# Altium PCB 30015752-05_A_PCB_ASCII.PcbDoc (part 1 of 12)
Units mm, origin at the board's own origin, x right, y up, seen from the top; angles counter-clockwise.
Board outline 100.05 x 72 mm, 10 copper layers (Top, GND_2, Signal_3, Signal_4, PWR_5, GND_6, Signal_7, Signal_8, GND_9, Bottom), stack 1.493 mm thick; 577 components, 546 nets, 2389 pads, 1412 vias.
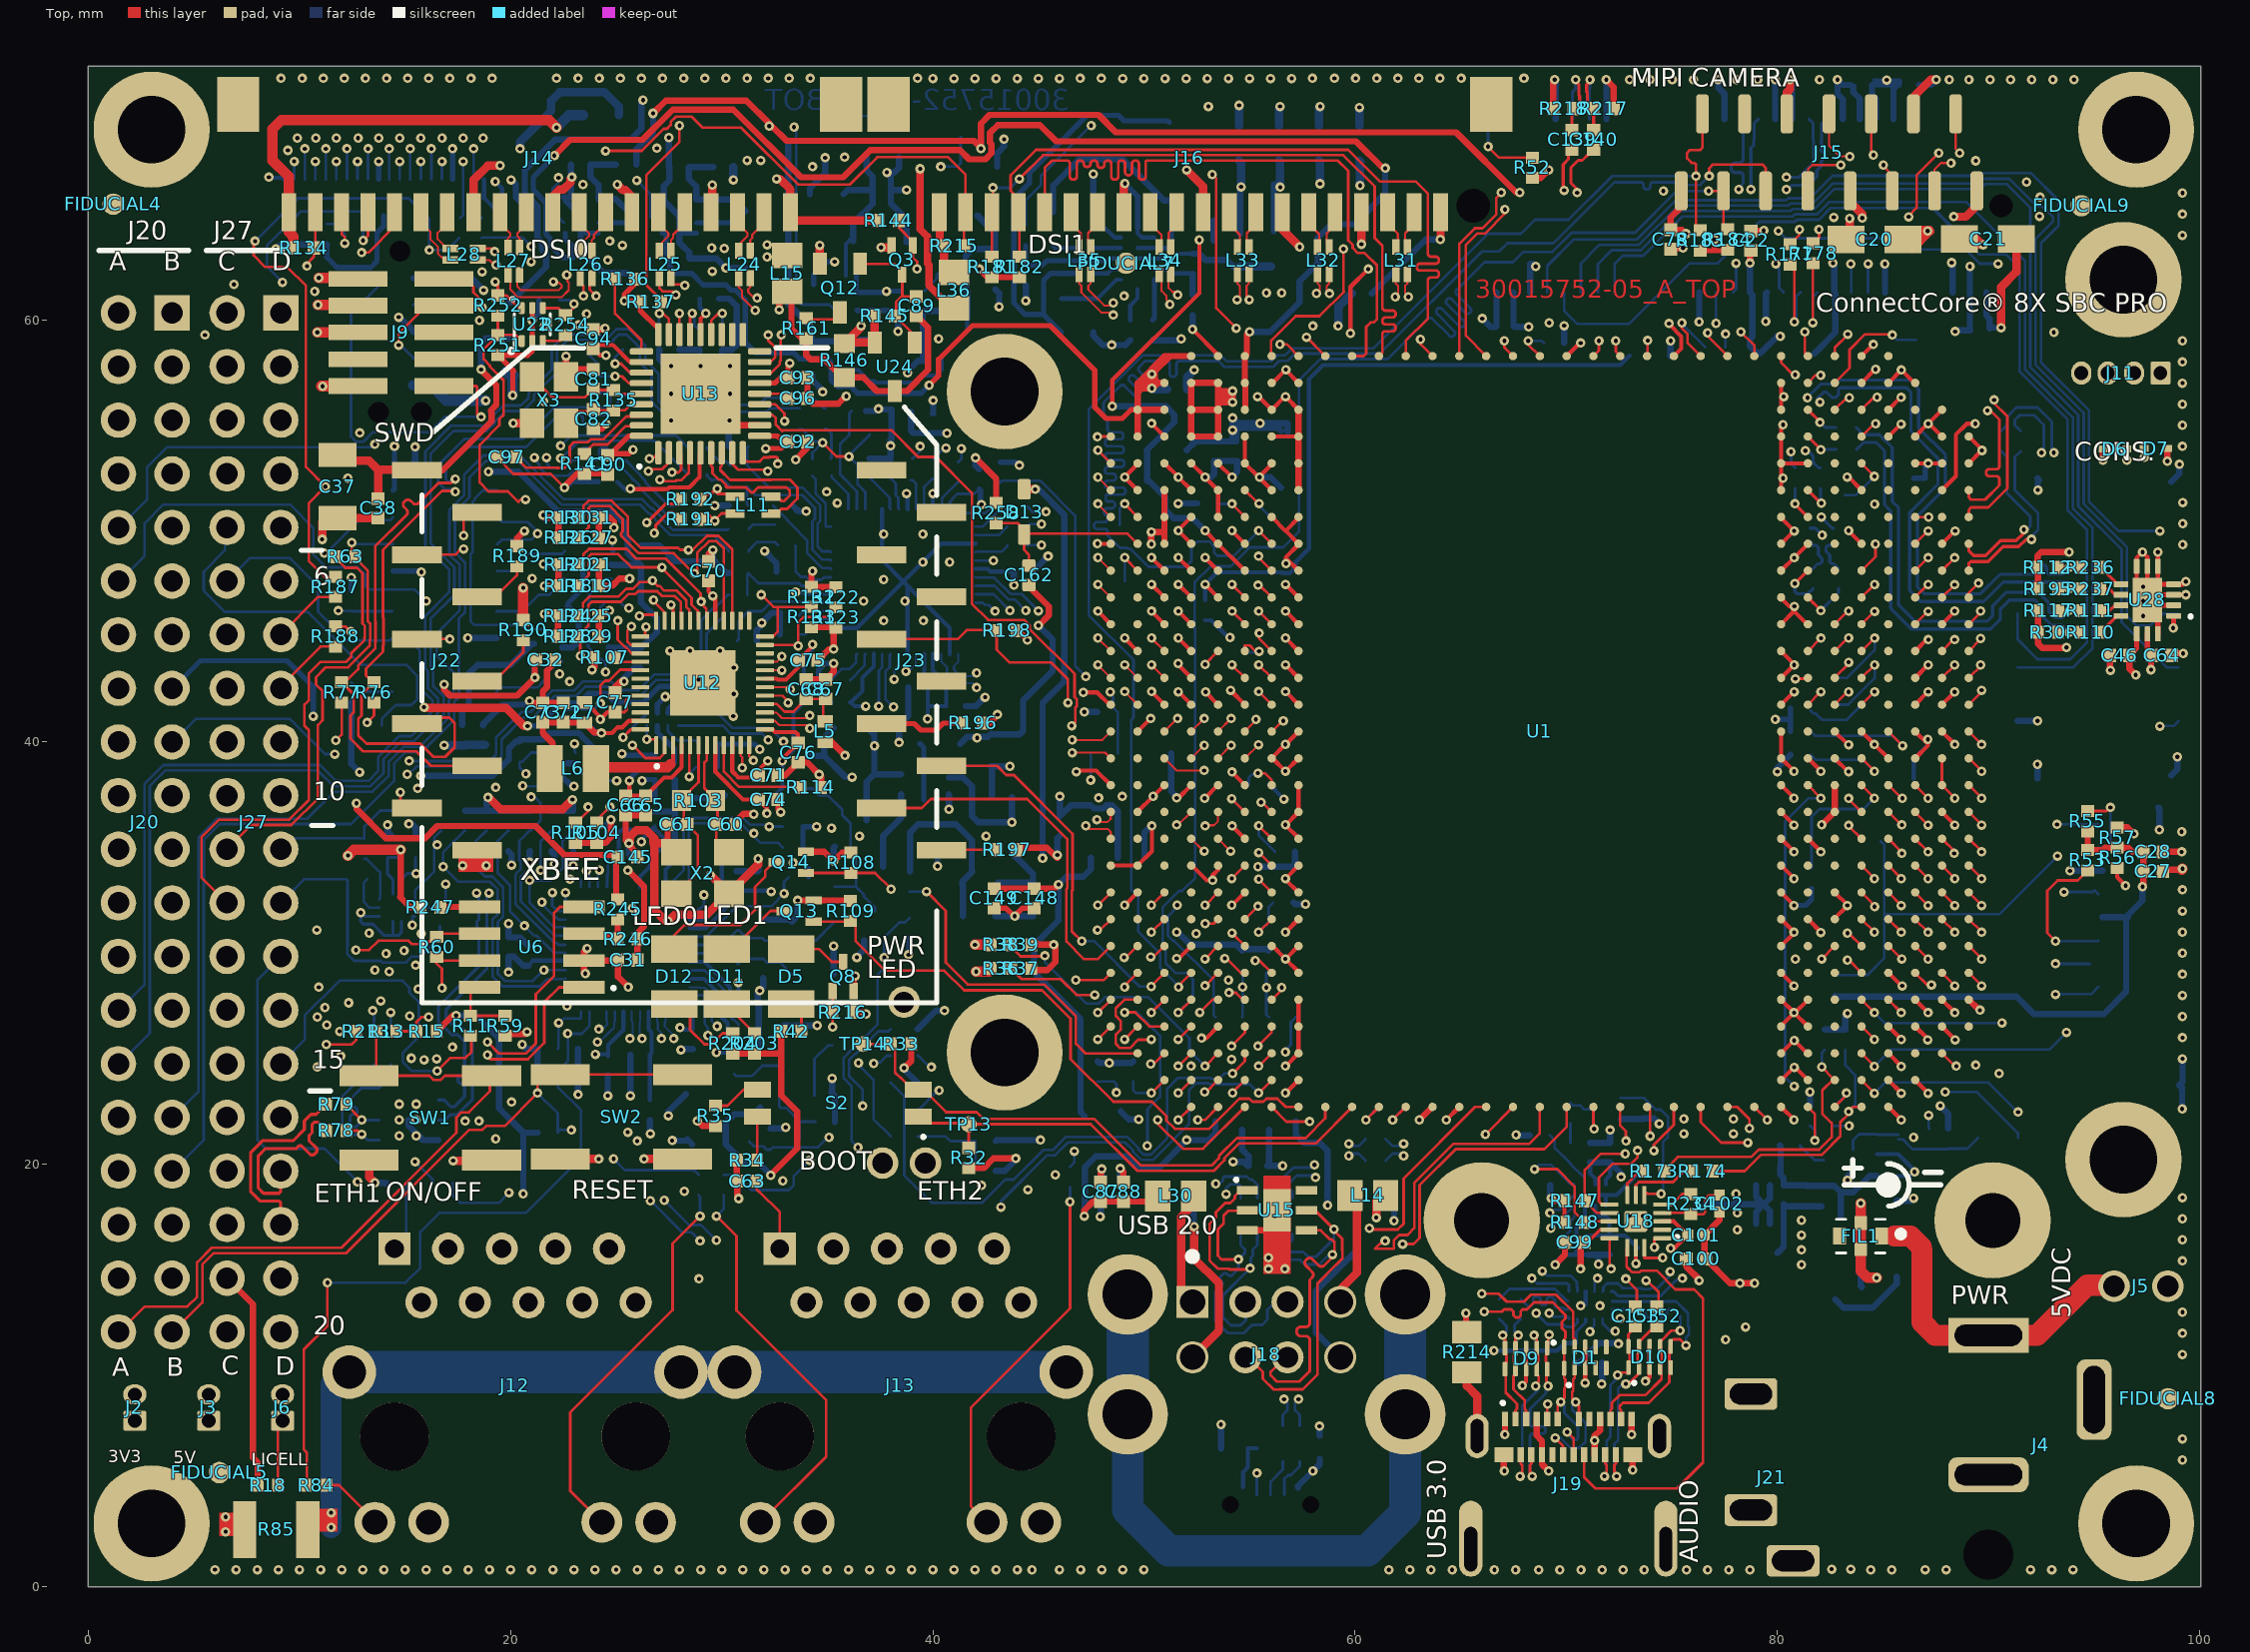
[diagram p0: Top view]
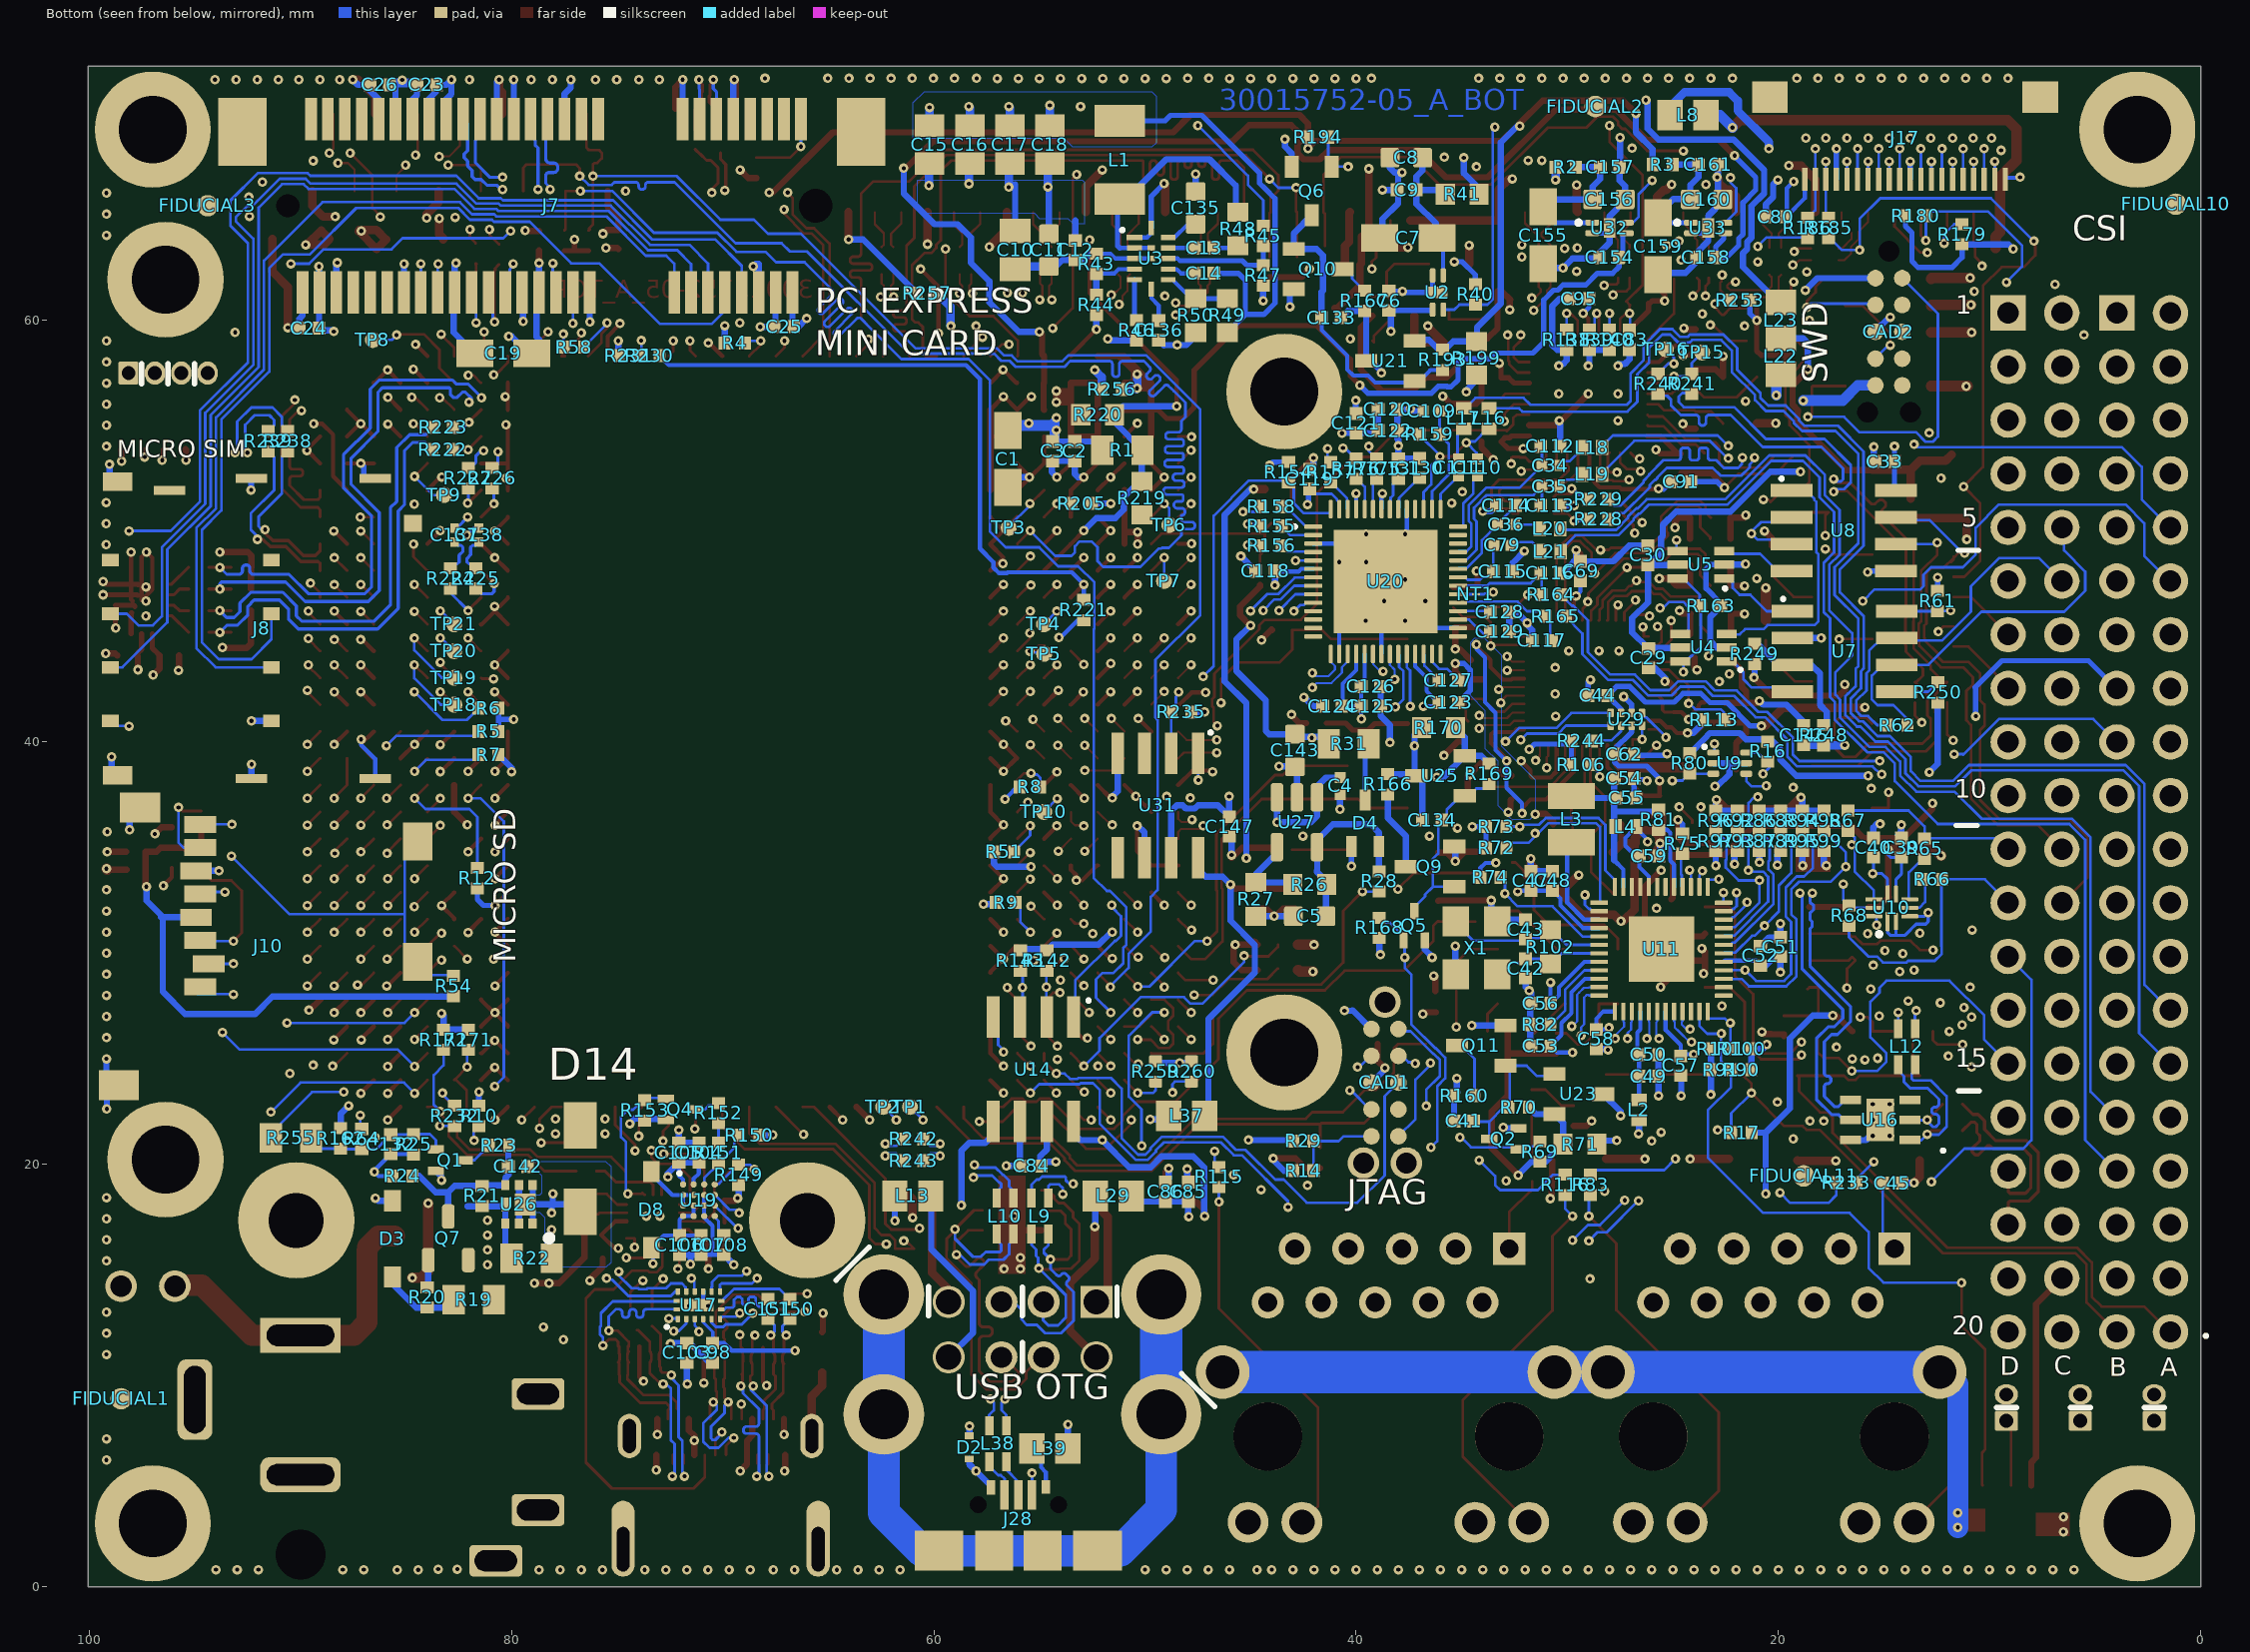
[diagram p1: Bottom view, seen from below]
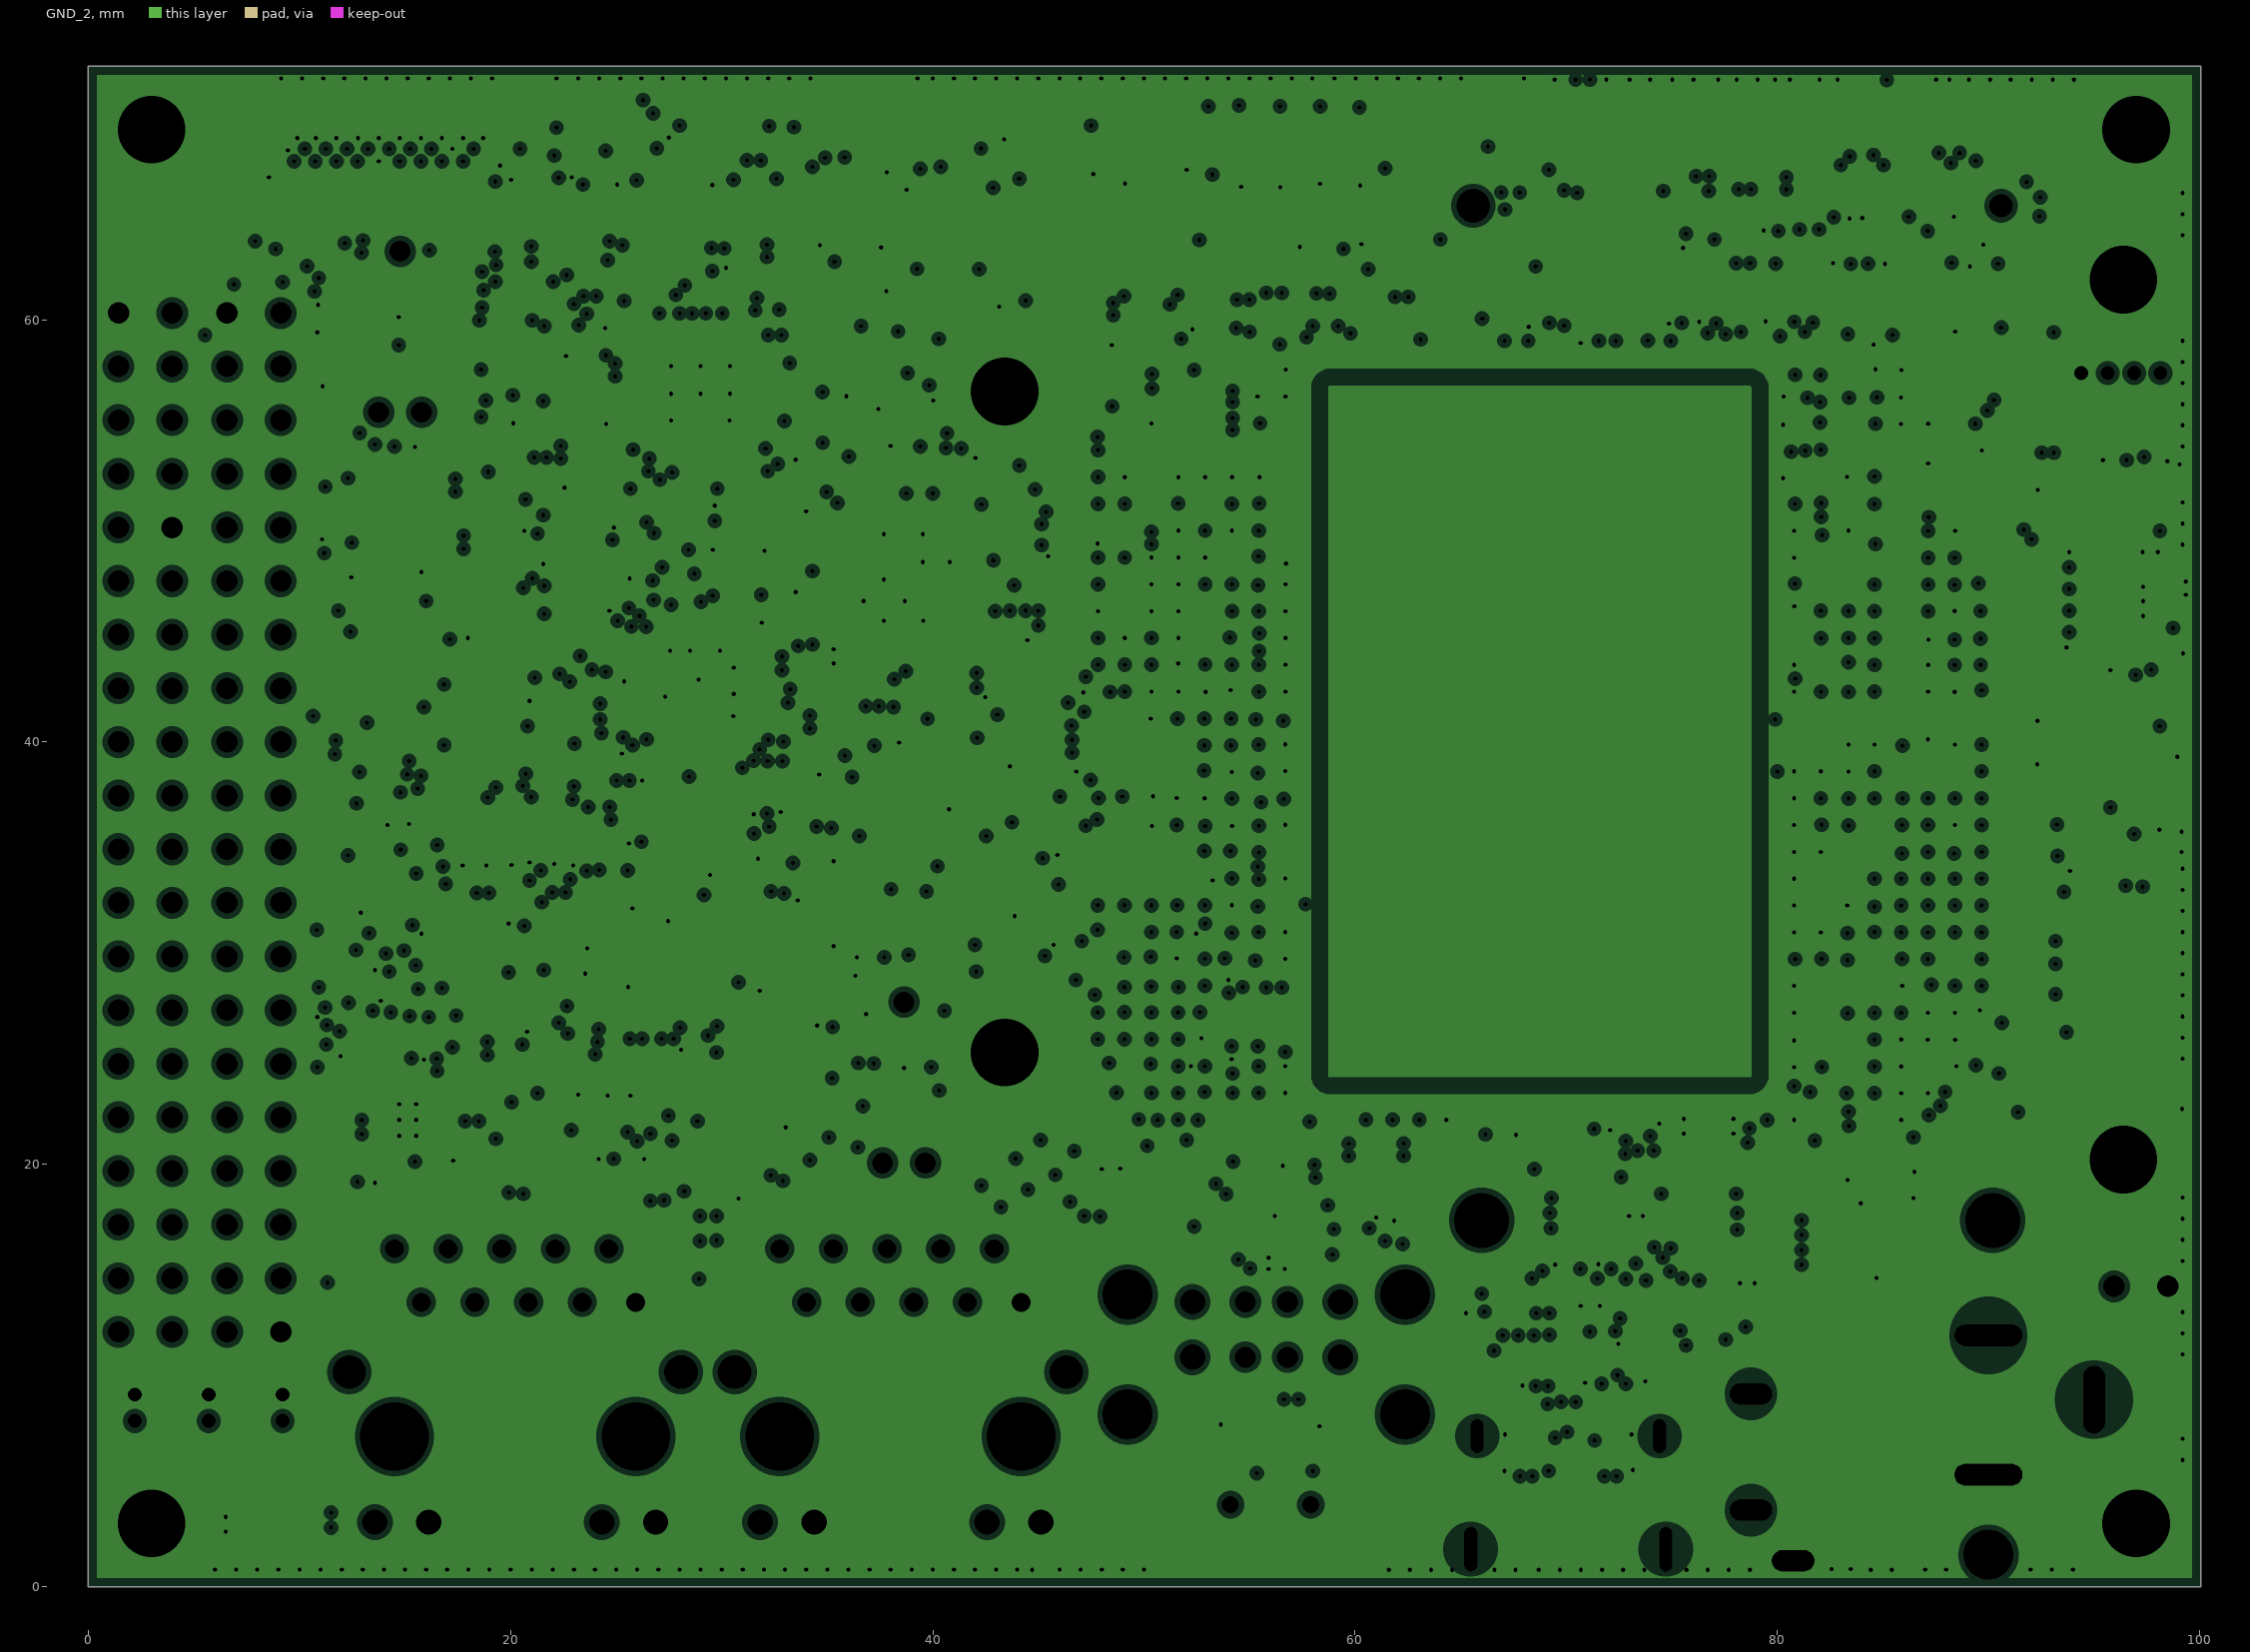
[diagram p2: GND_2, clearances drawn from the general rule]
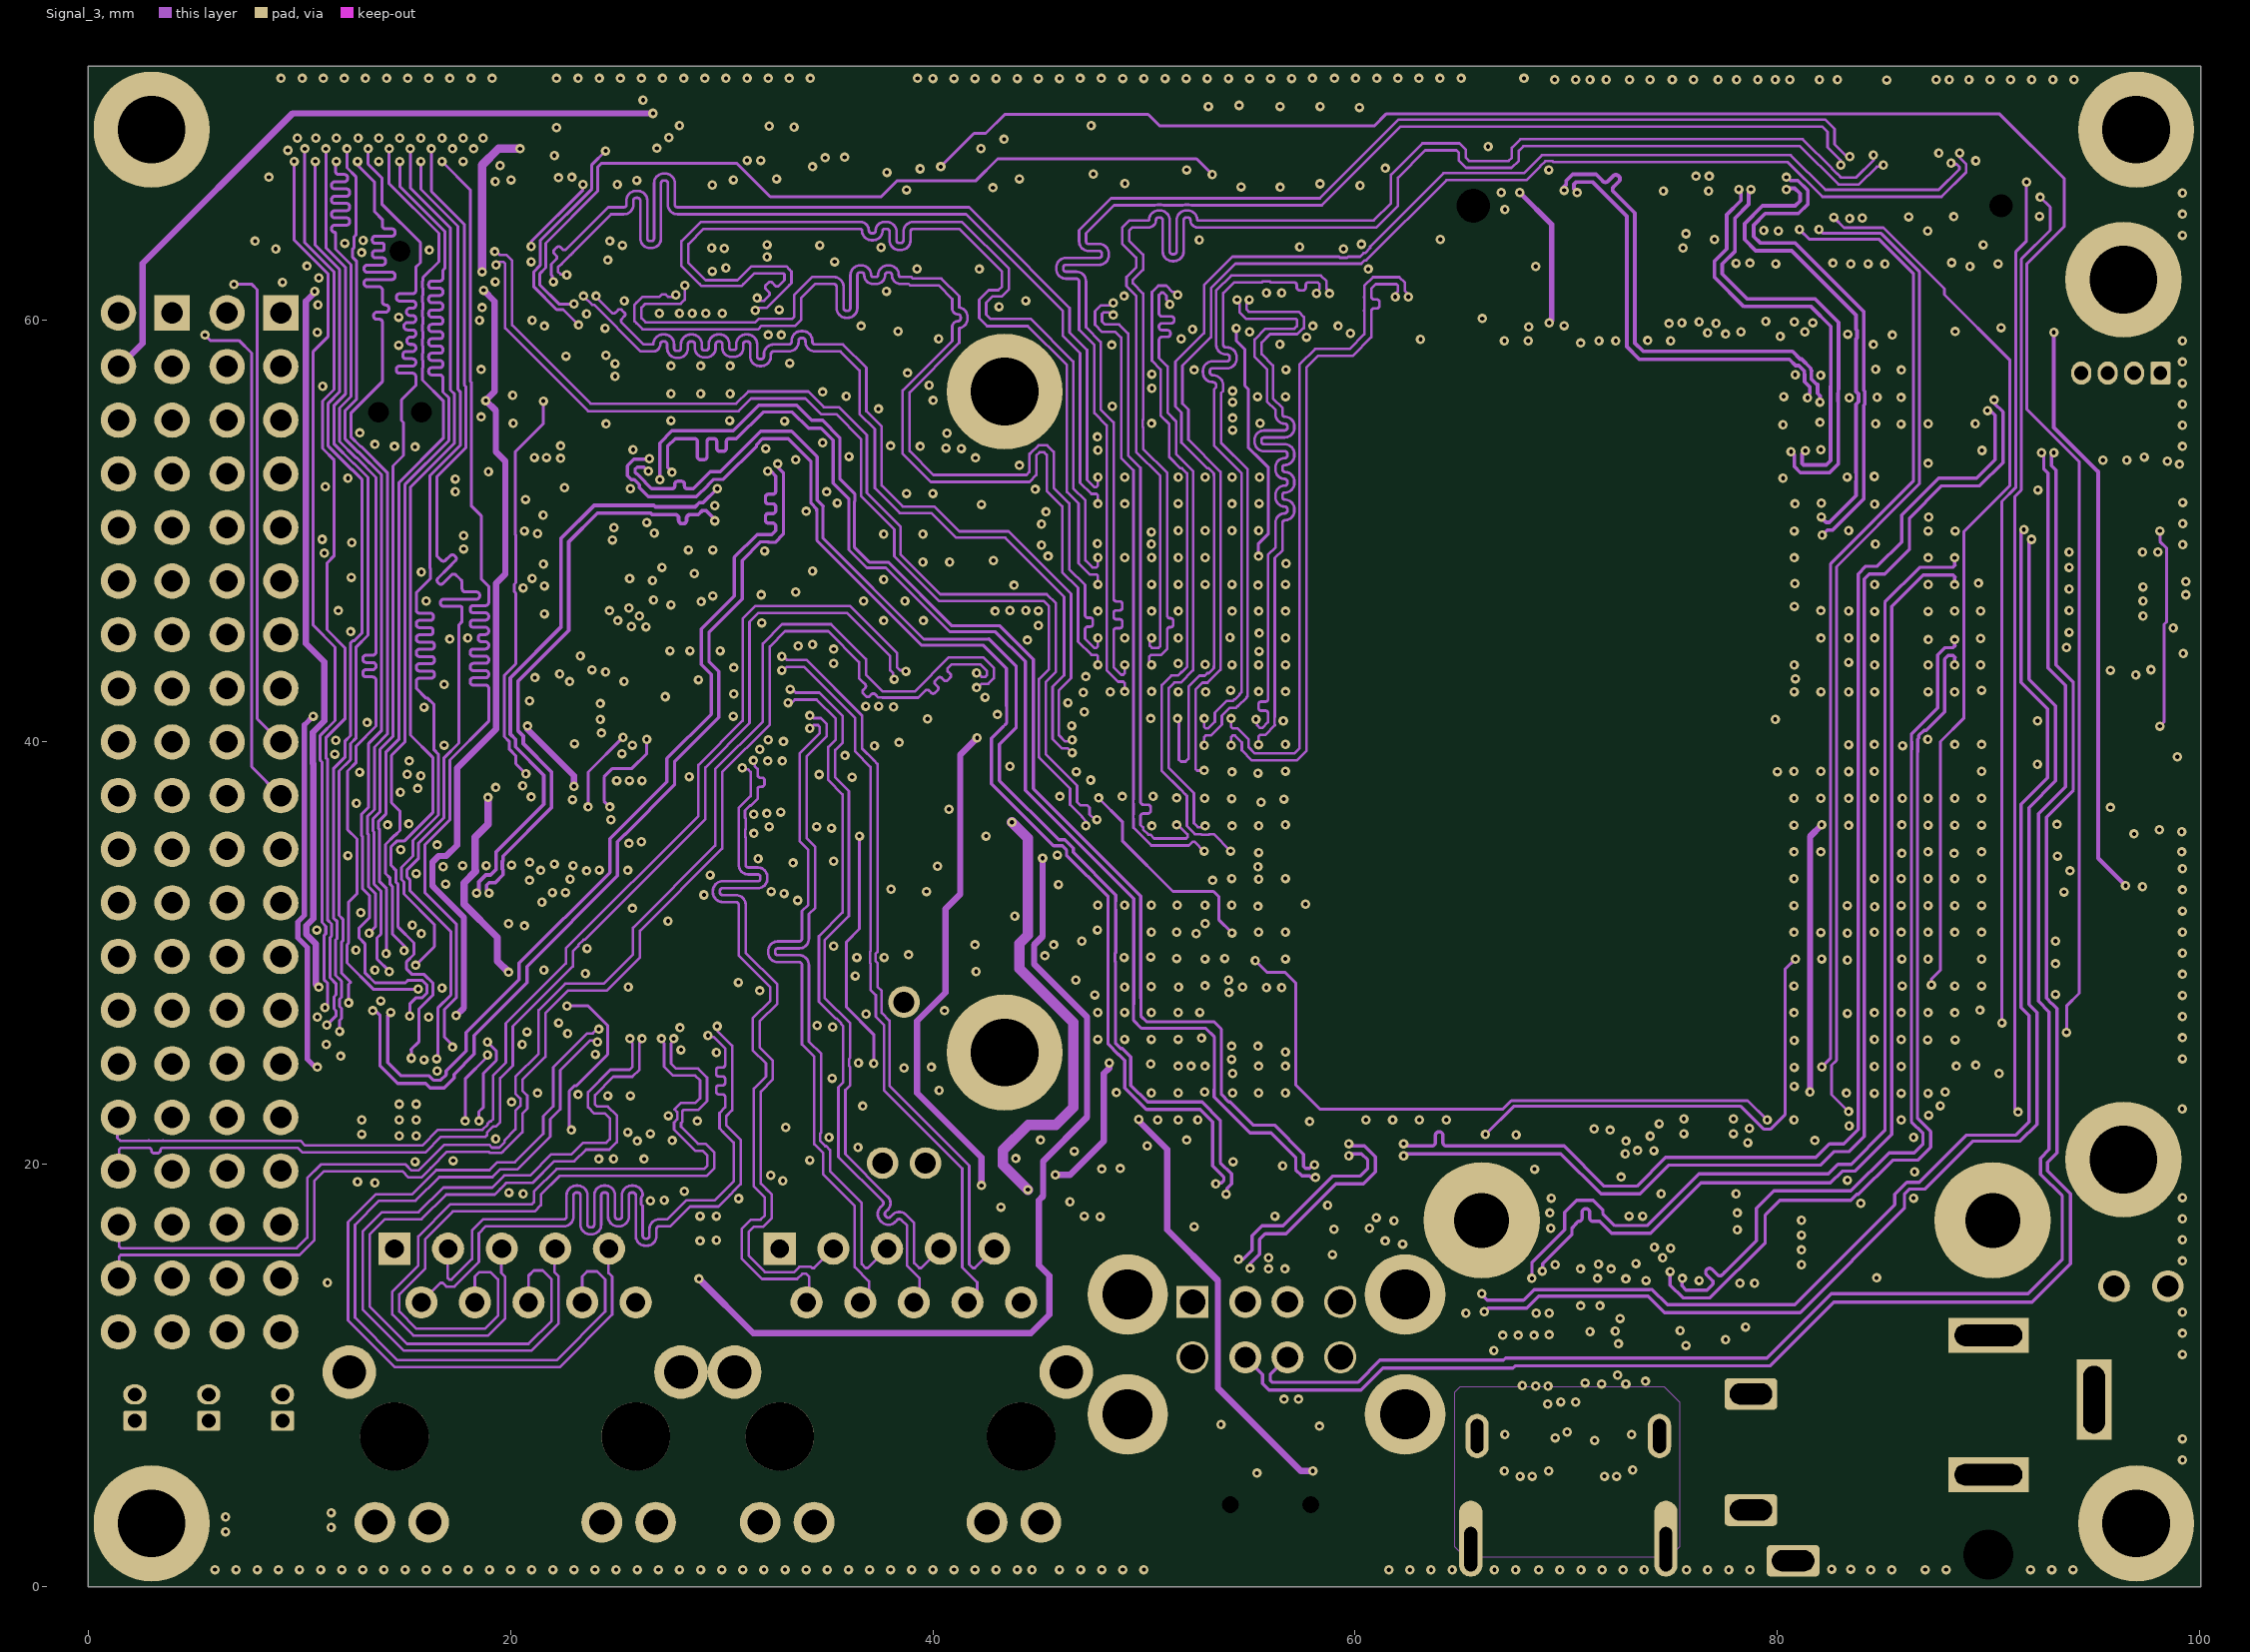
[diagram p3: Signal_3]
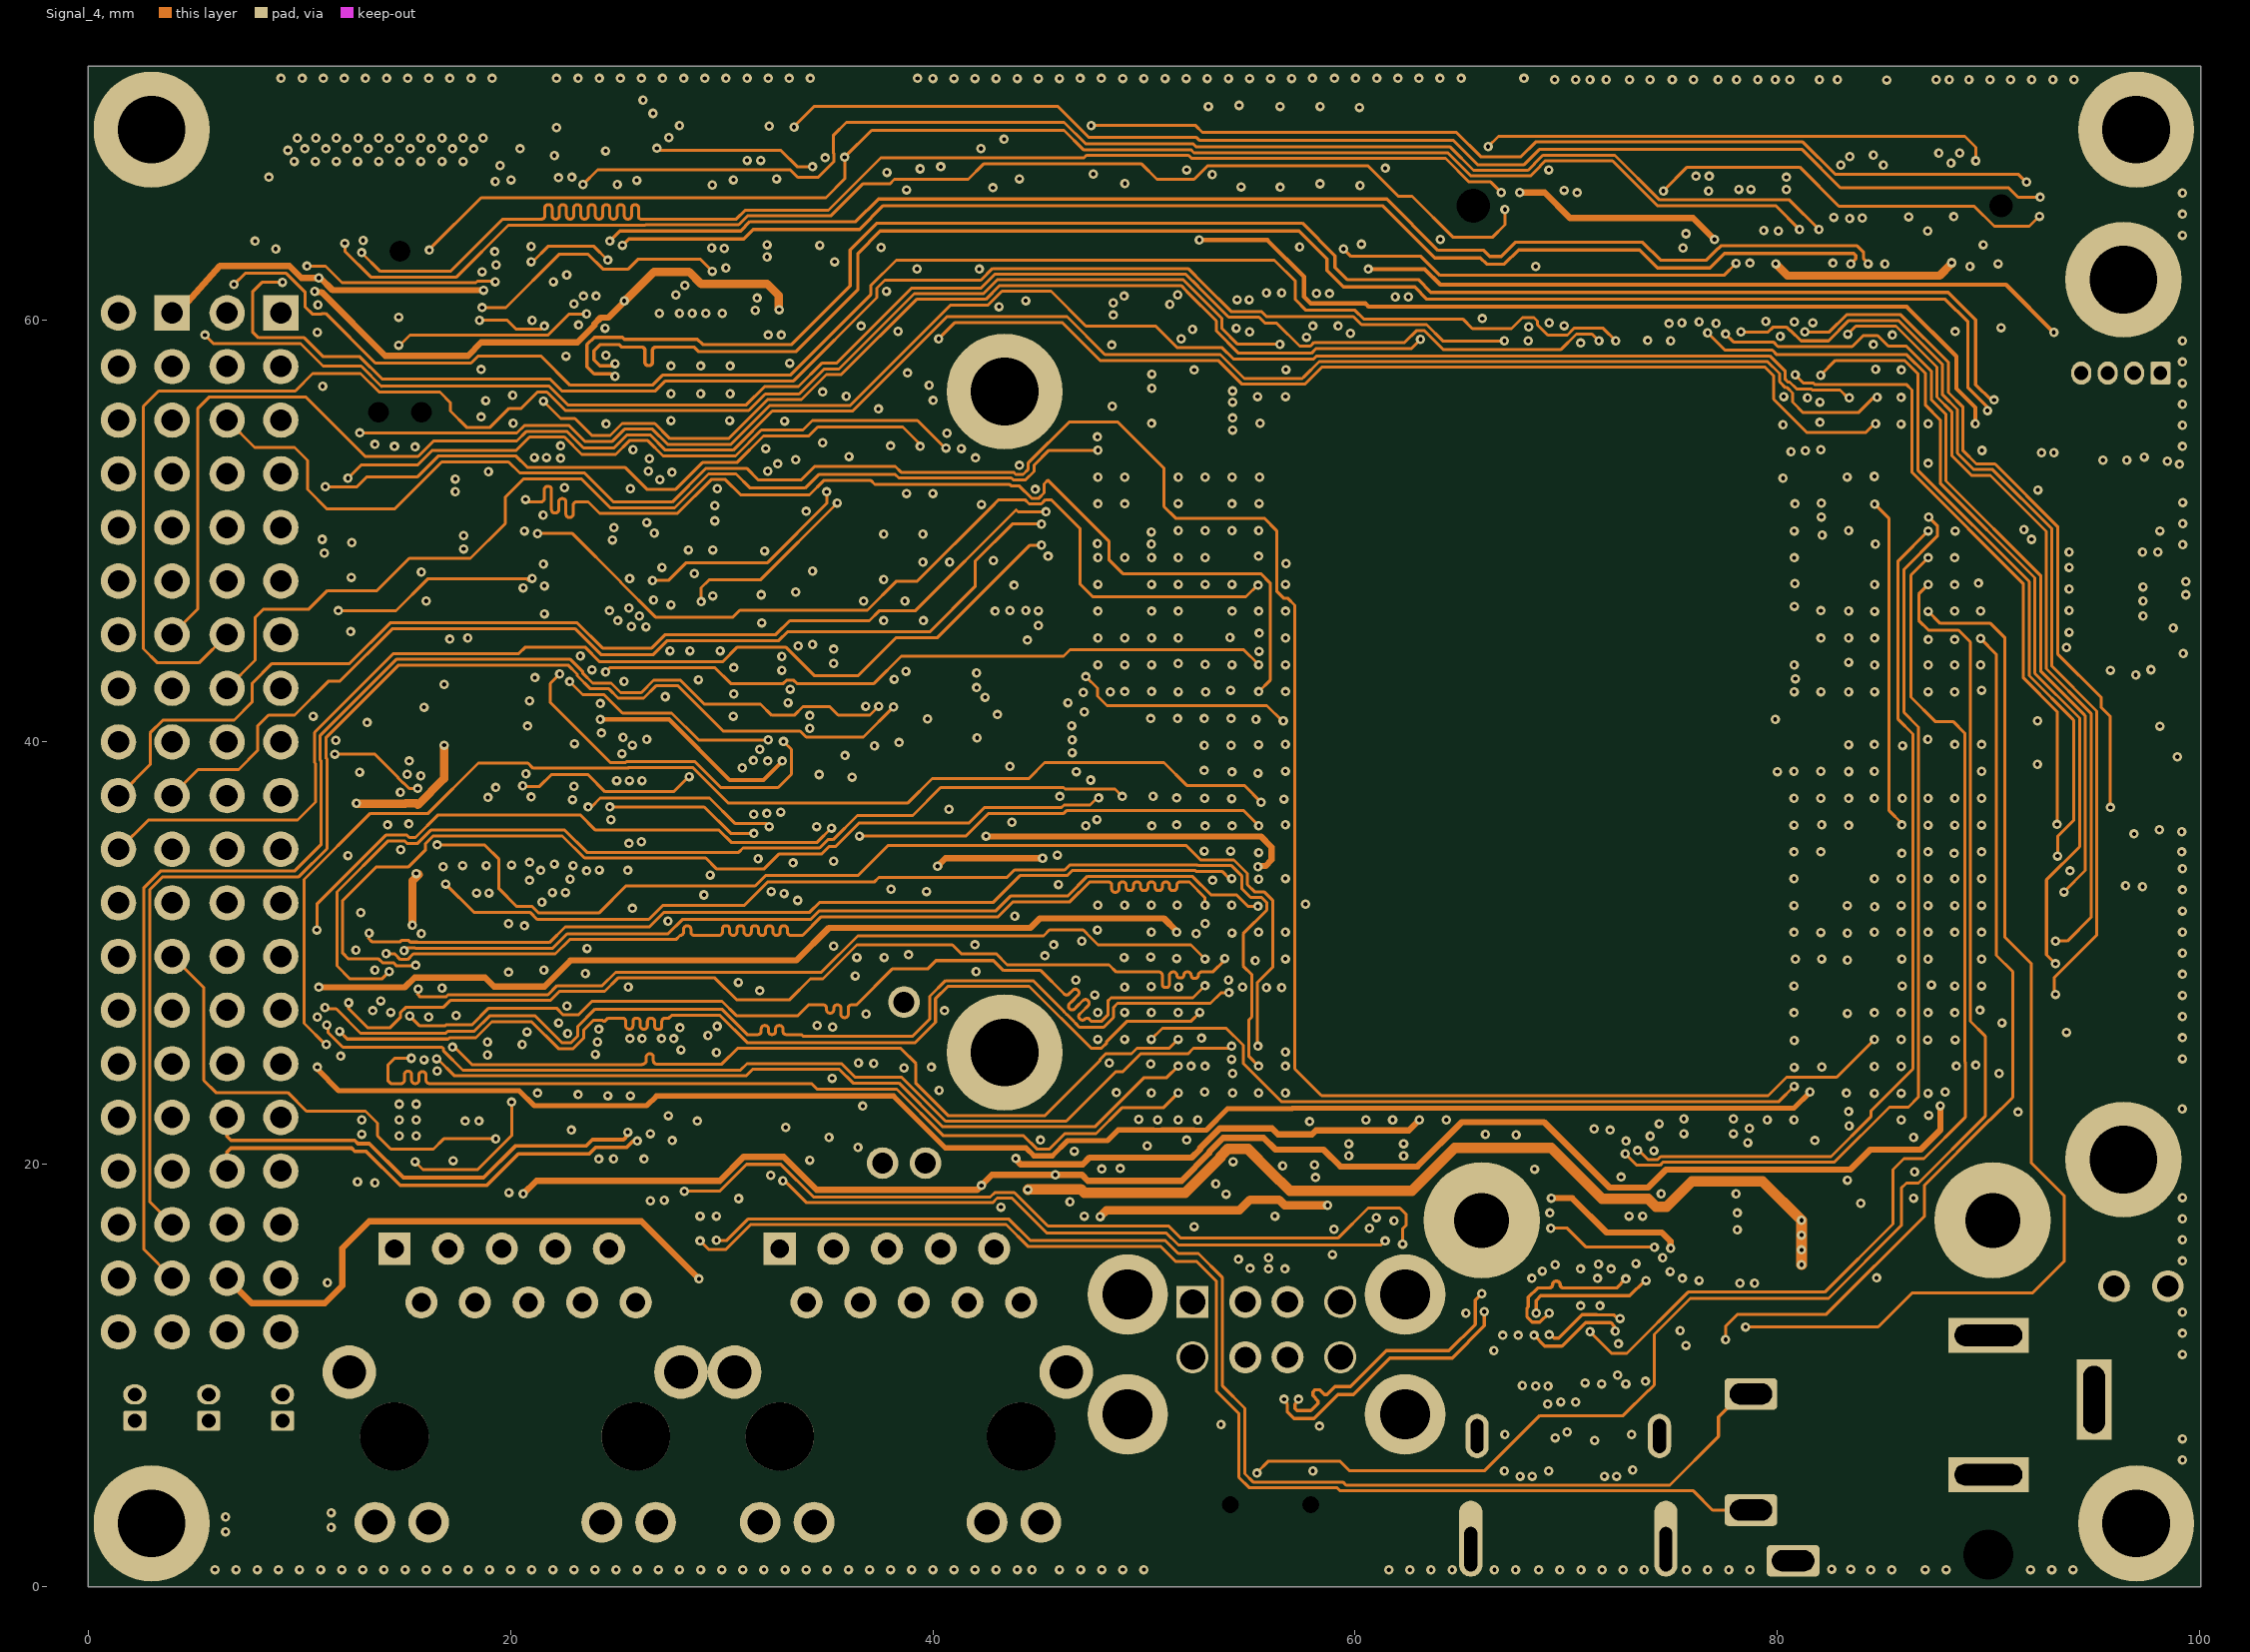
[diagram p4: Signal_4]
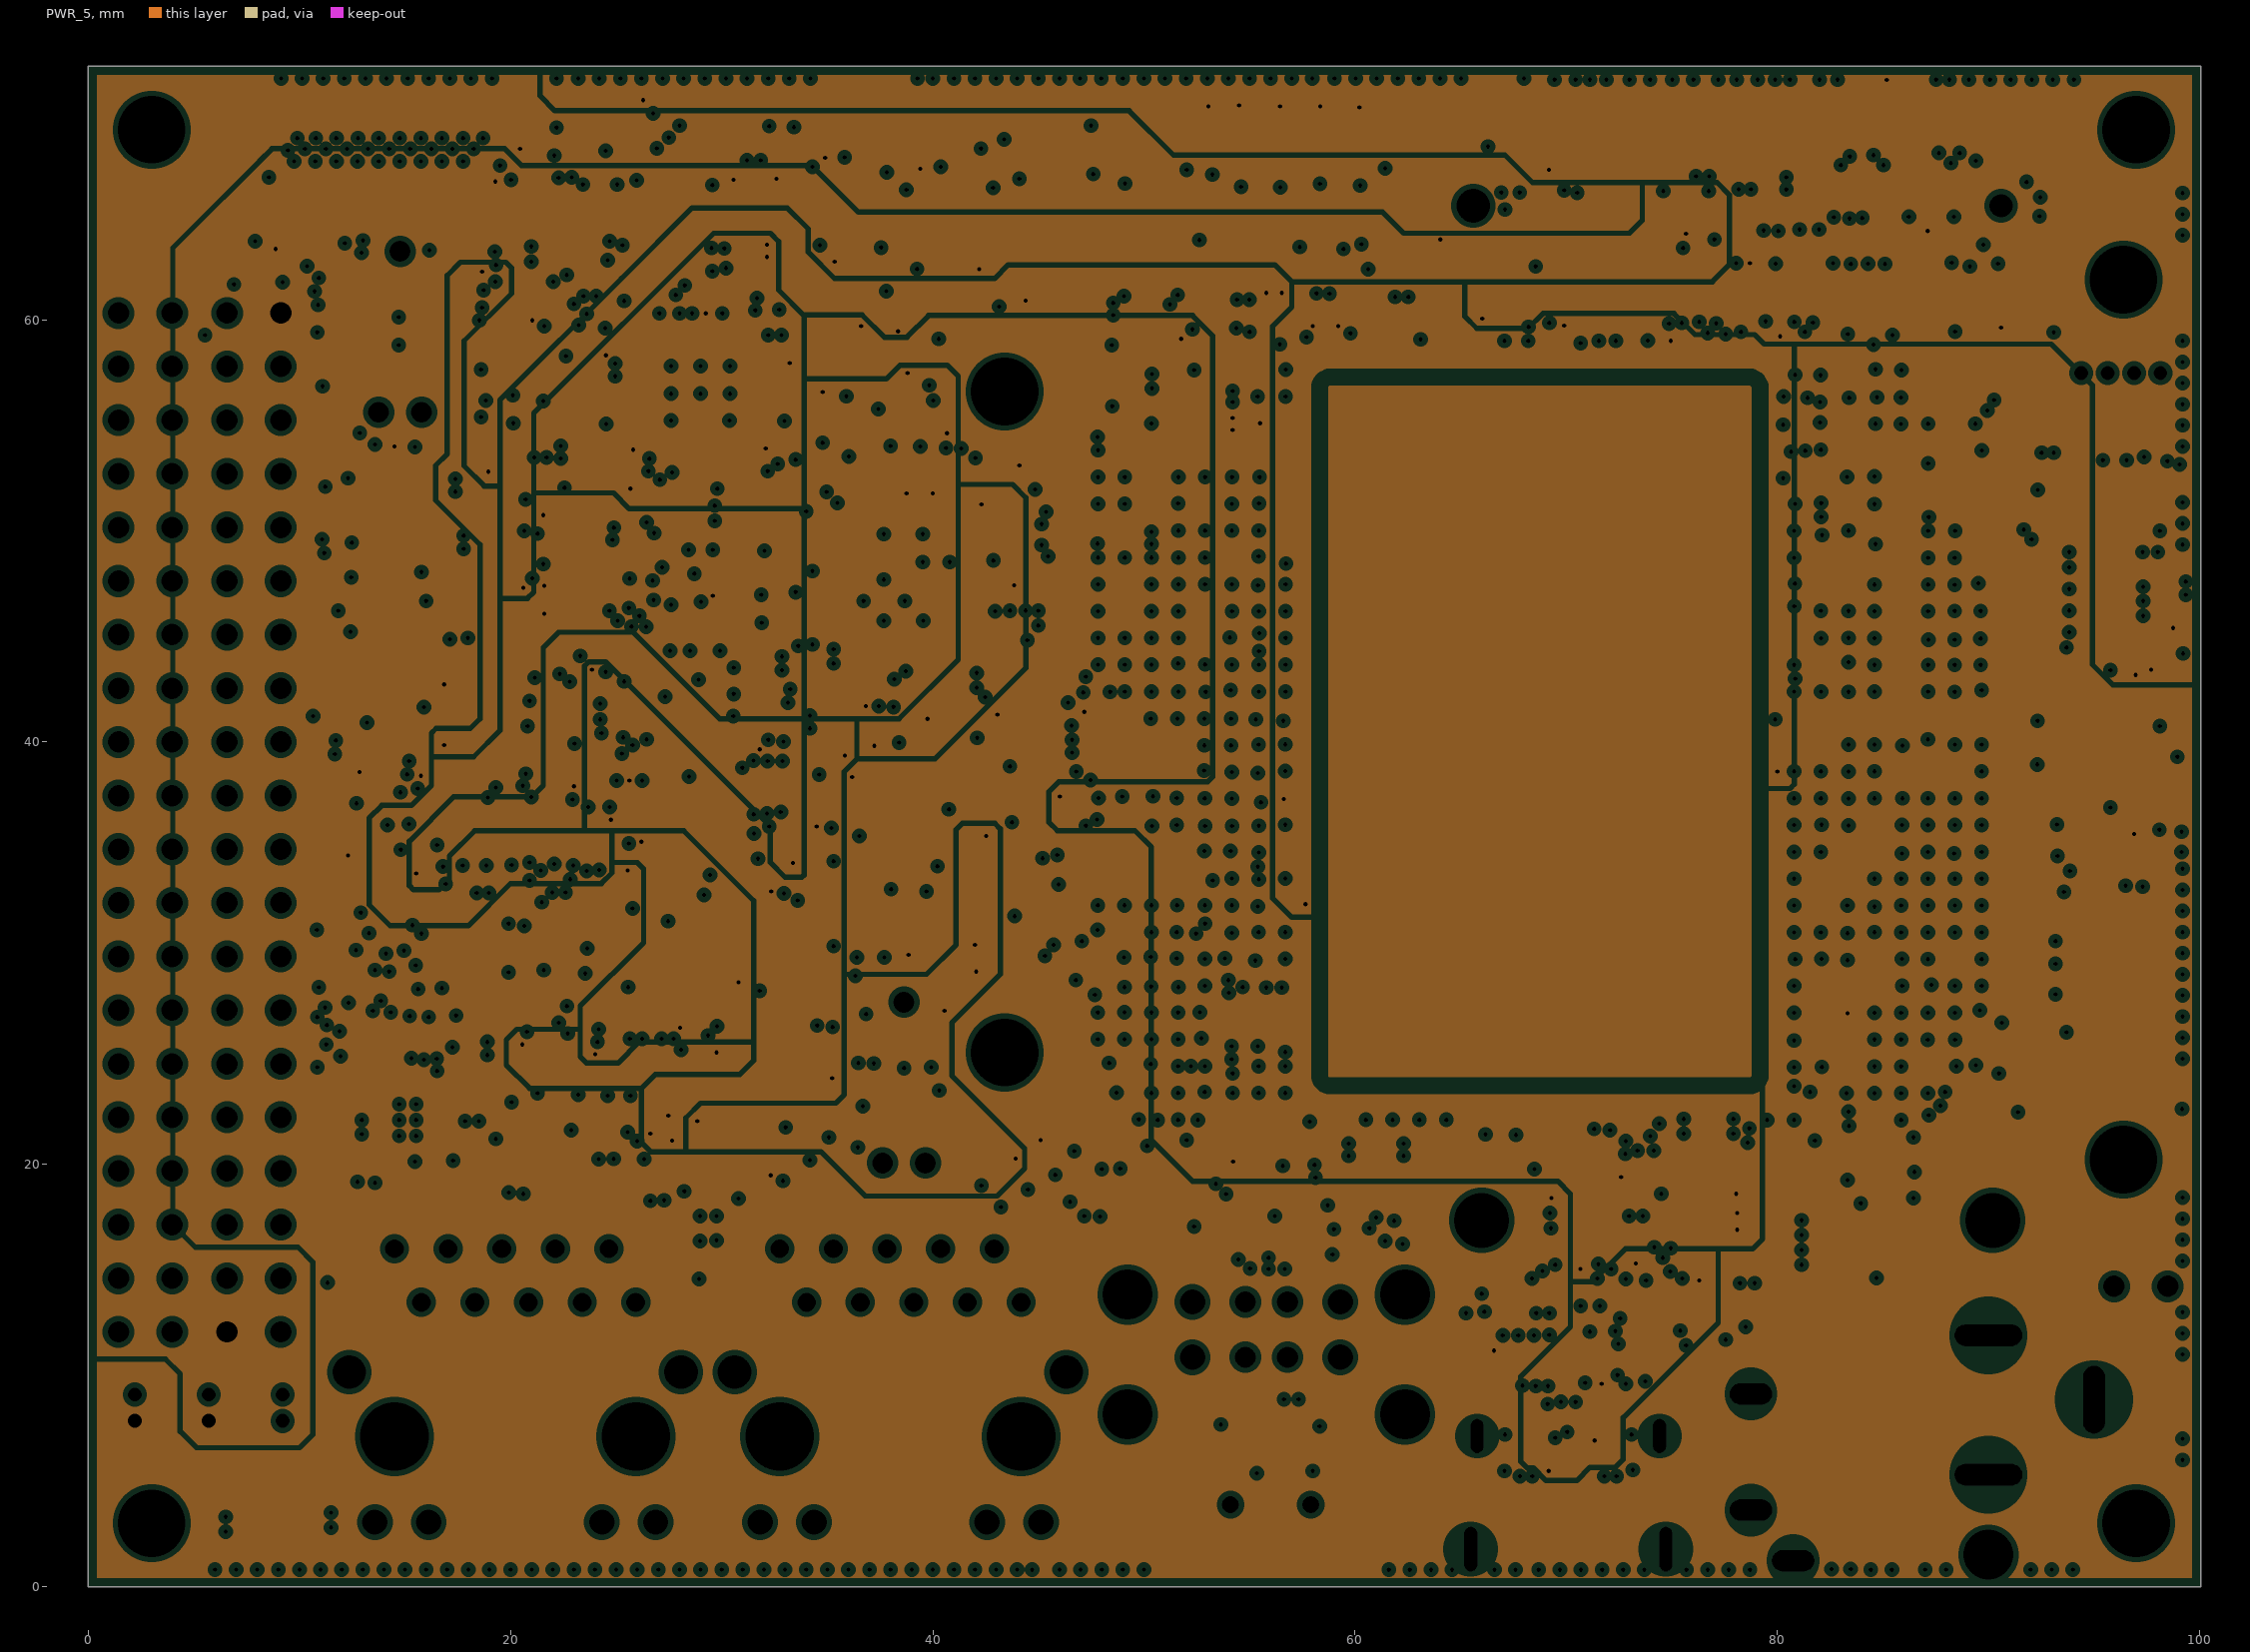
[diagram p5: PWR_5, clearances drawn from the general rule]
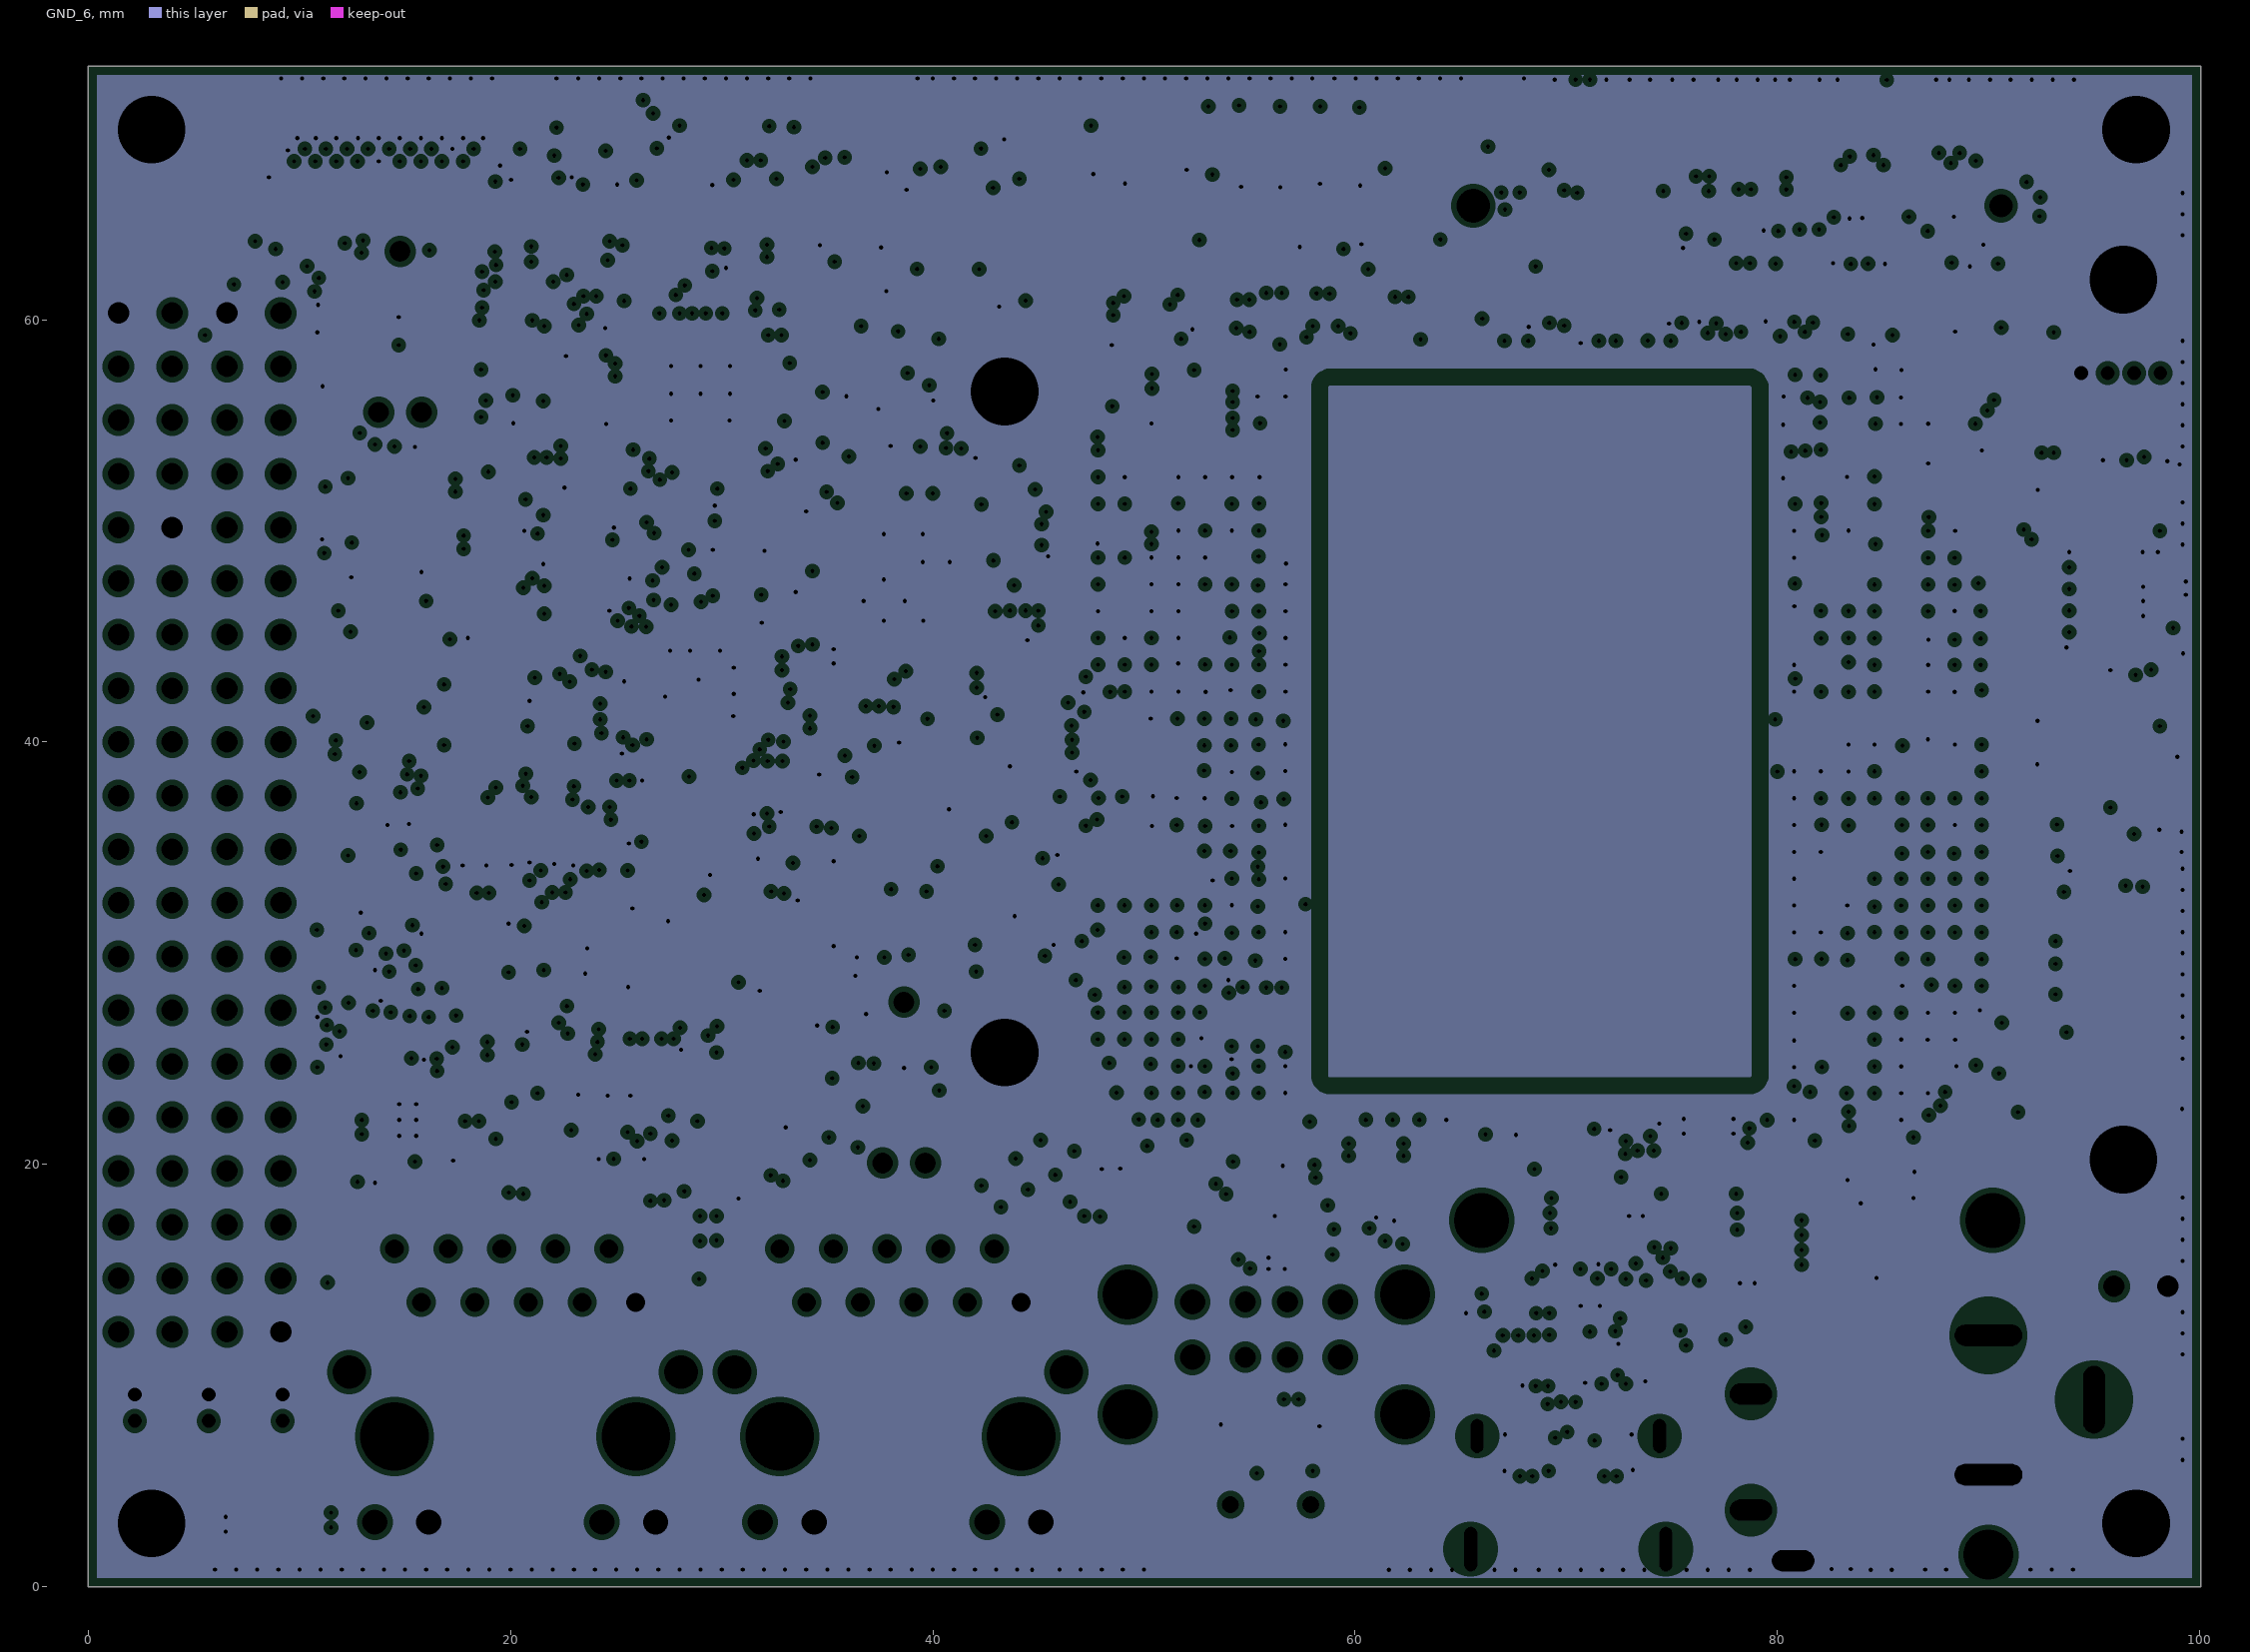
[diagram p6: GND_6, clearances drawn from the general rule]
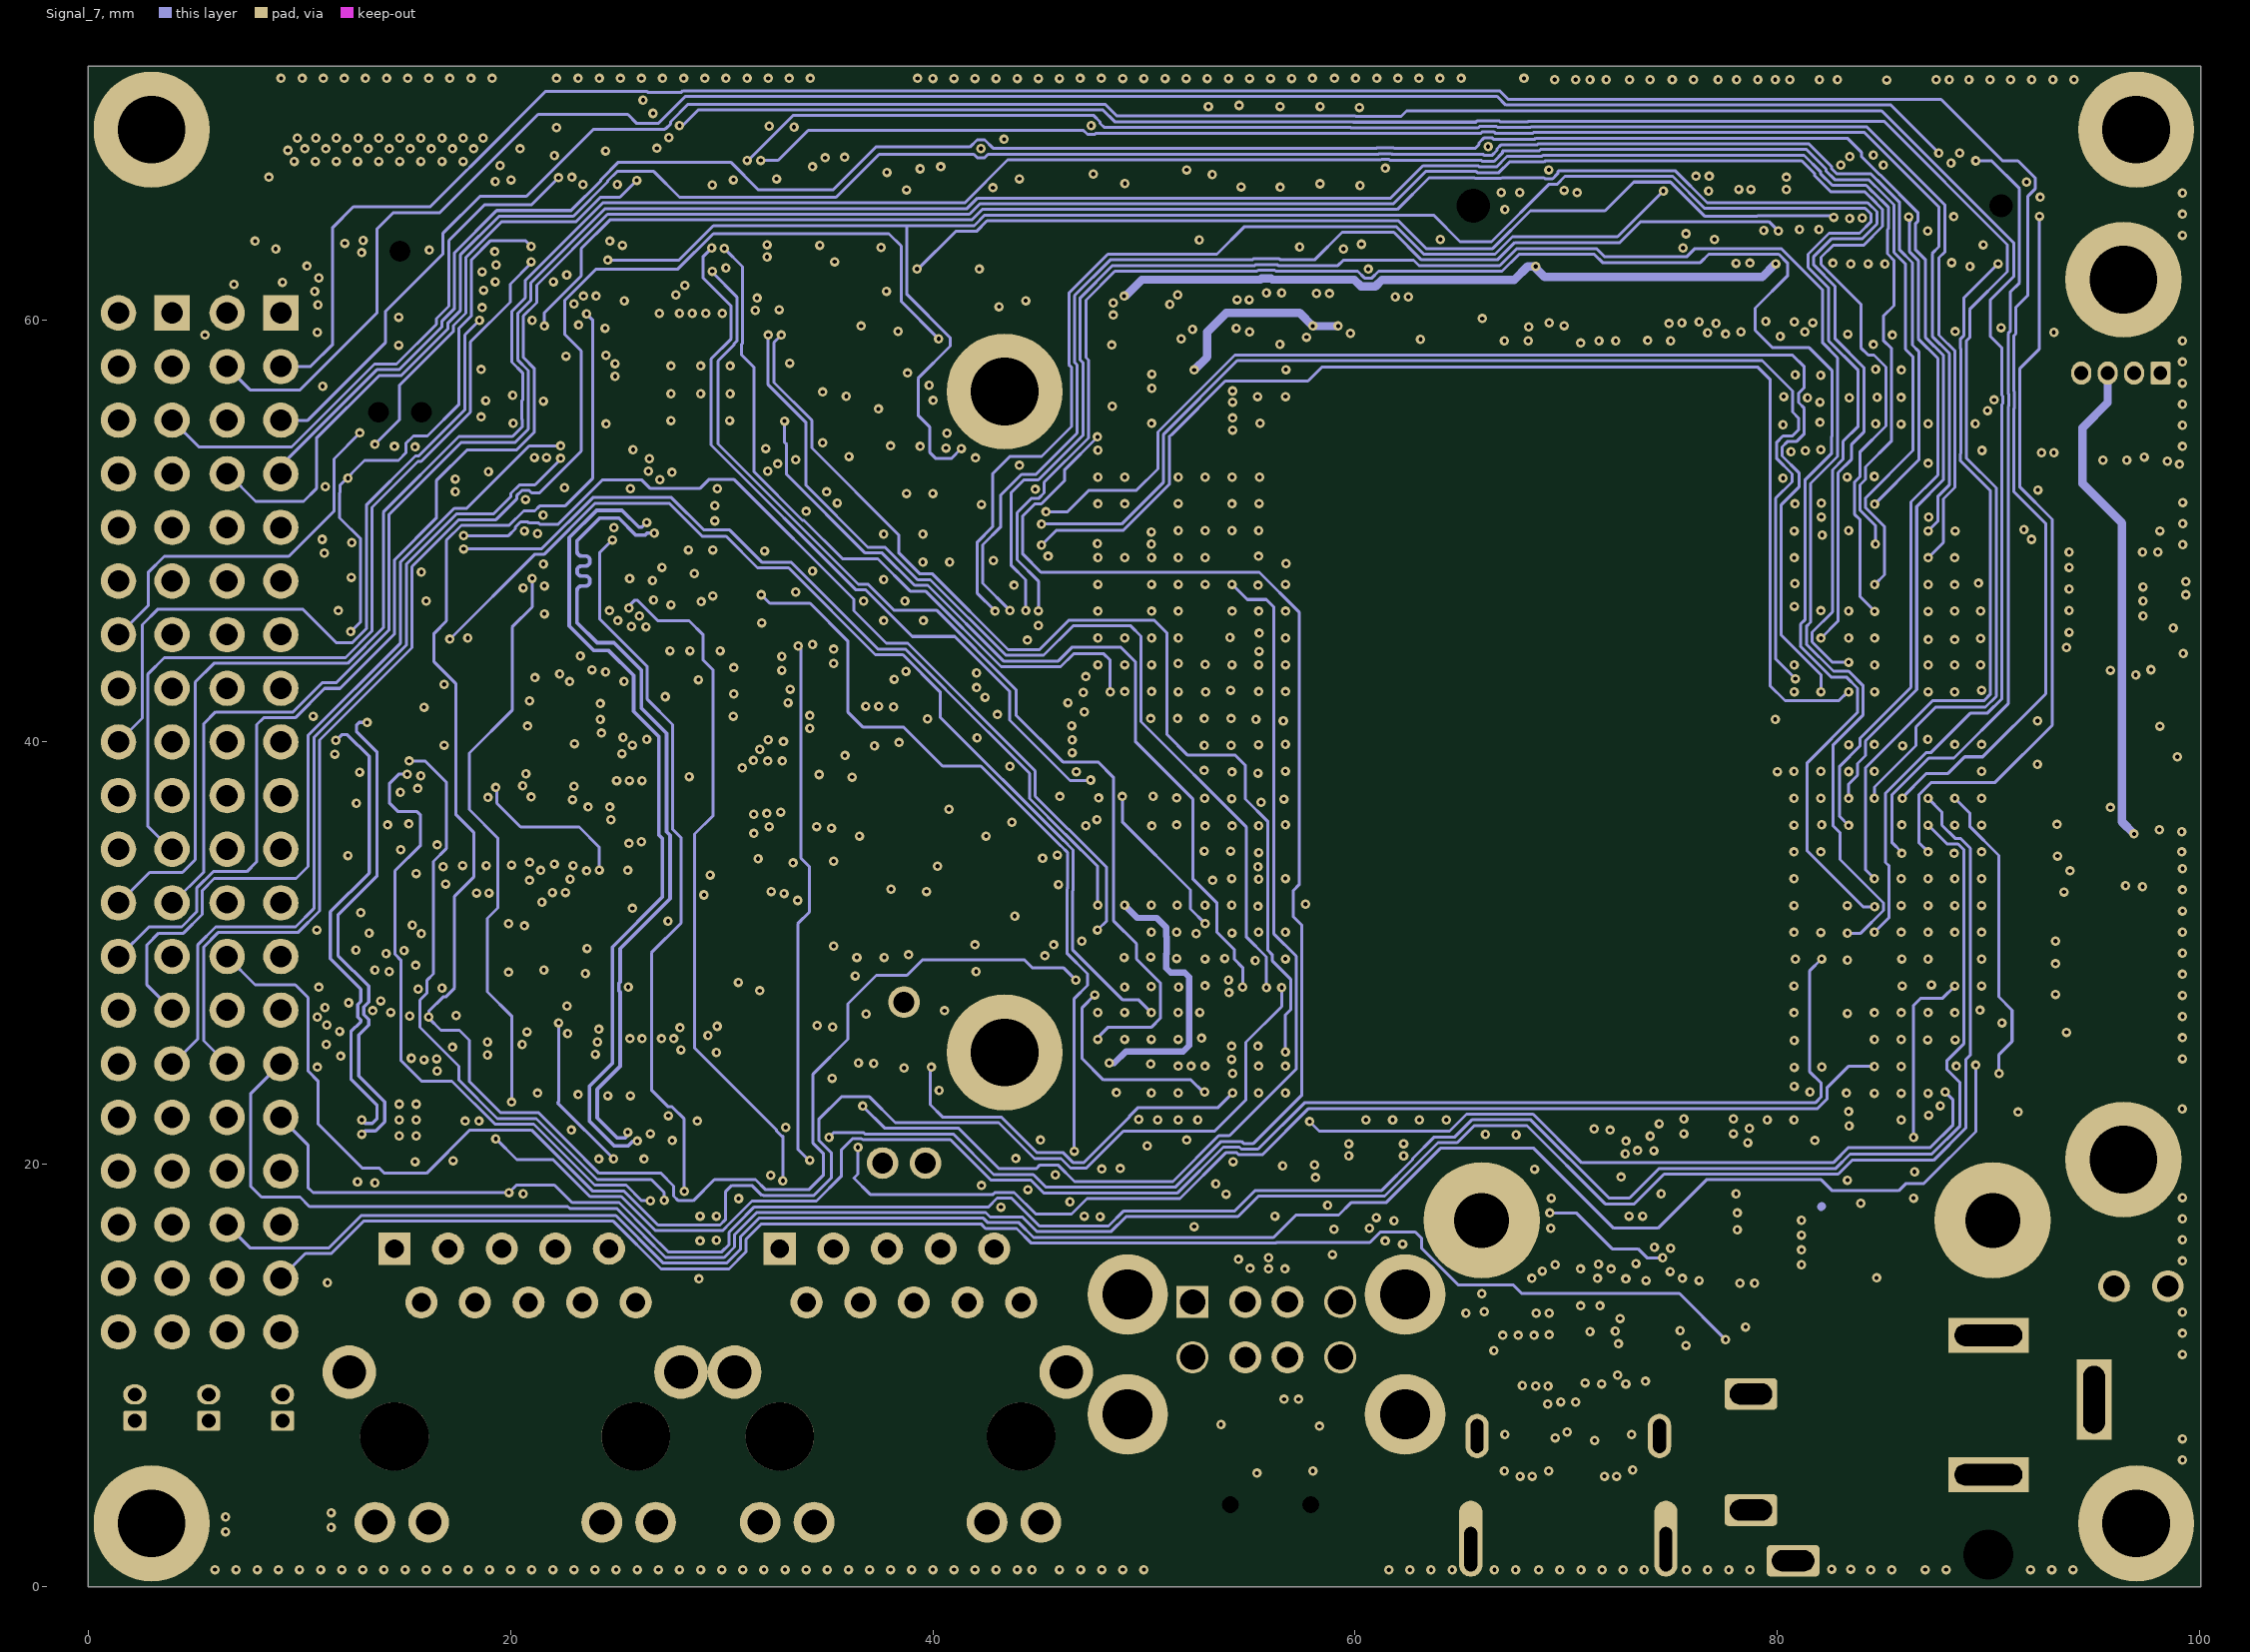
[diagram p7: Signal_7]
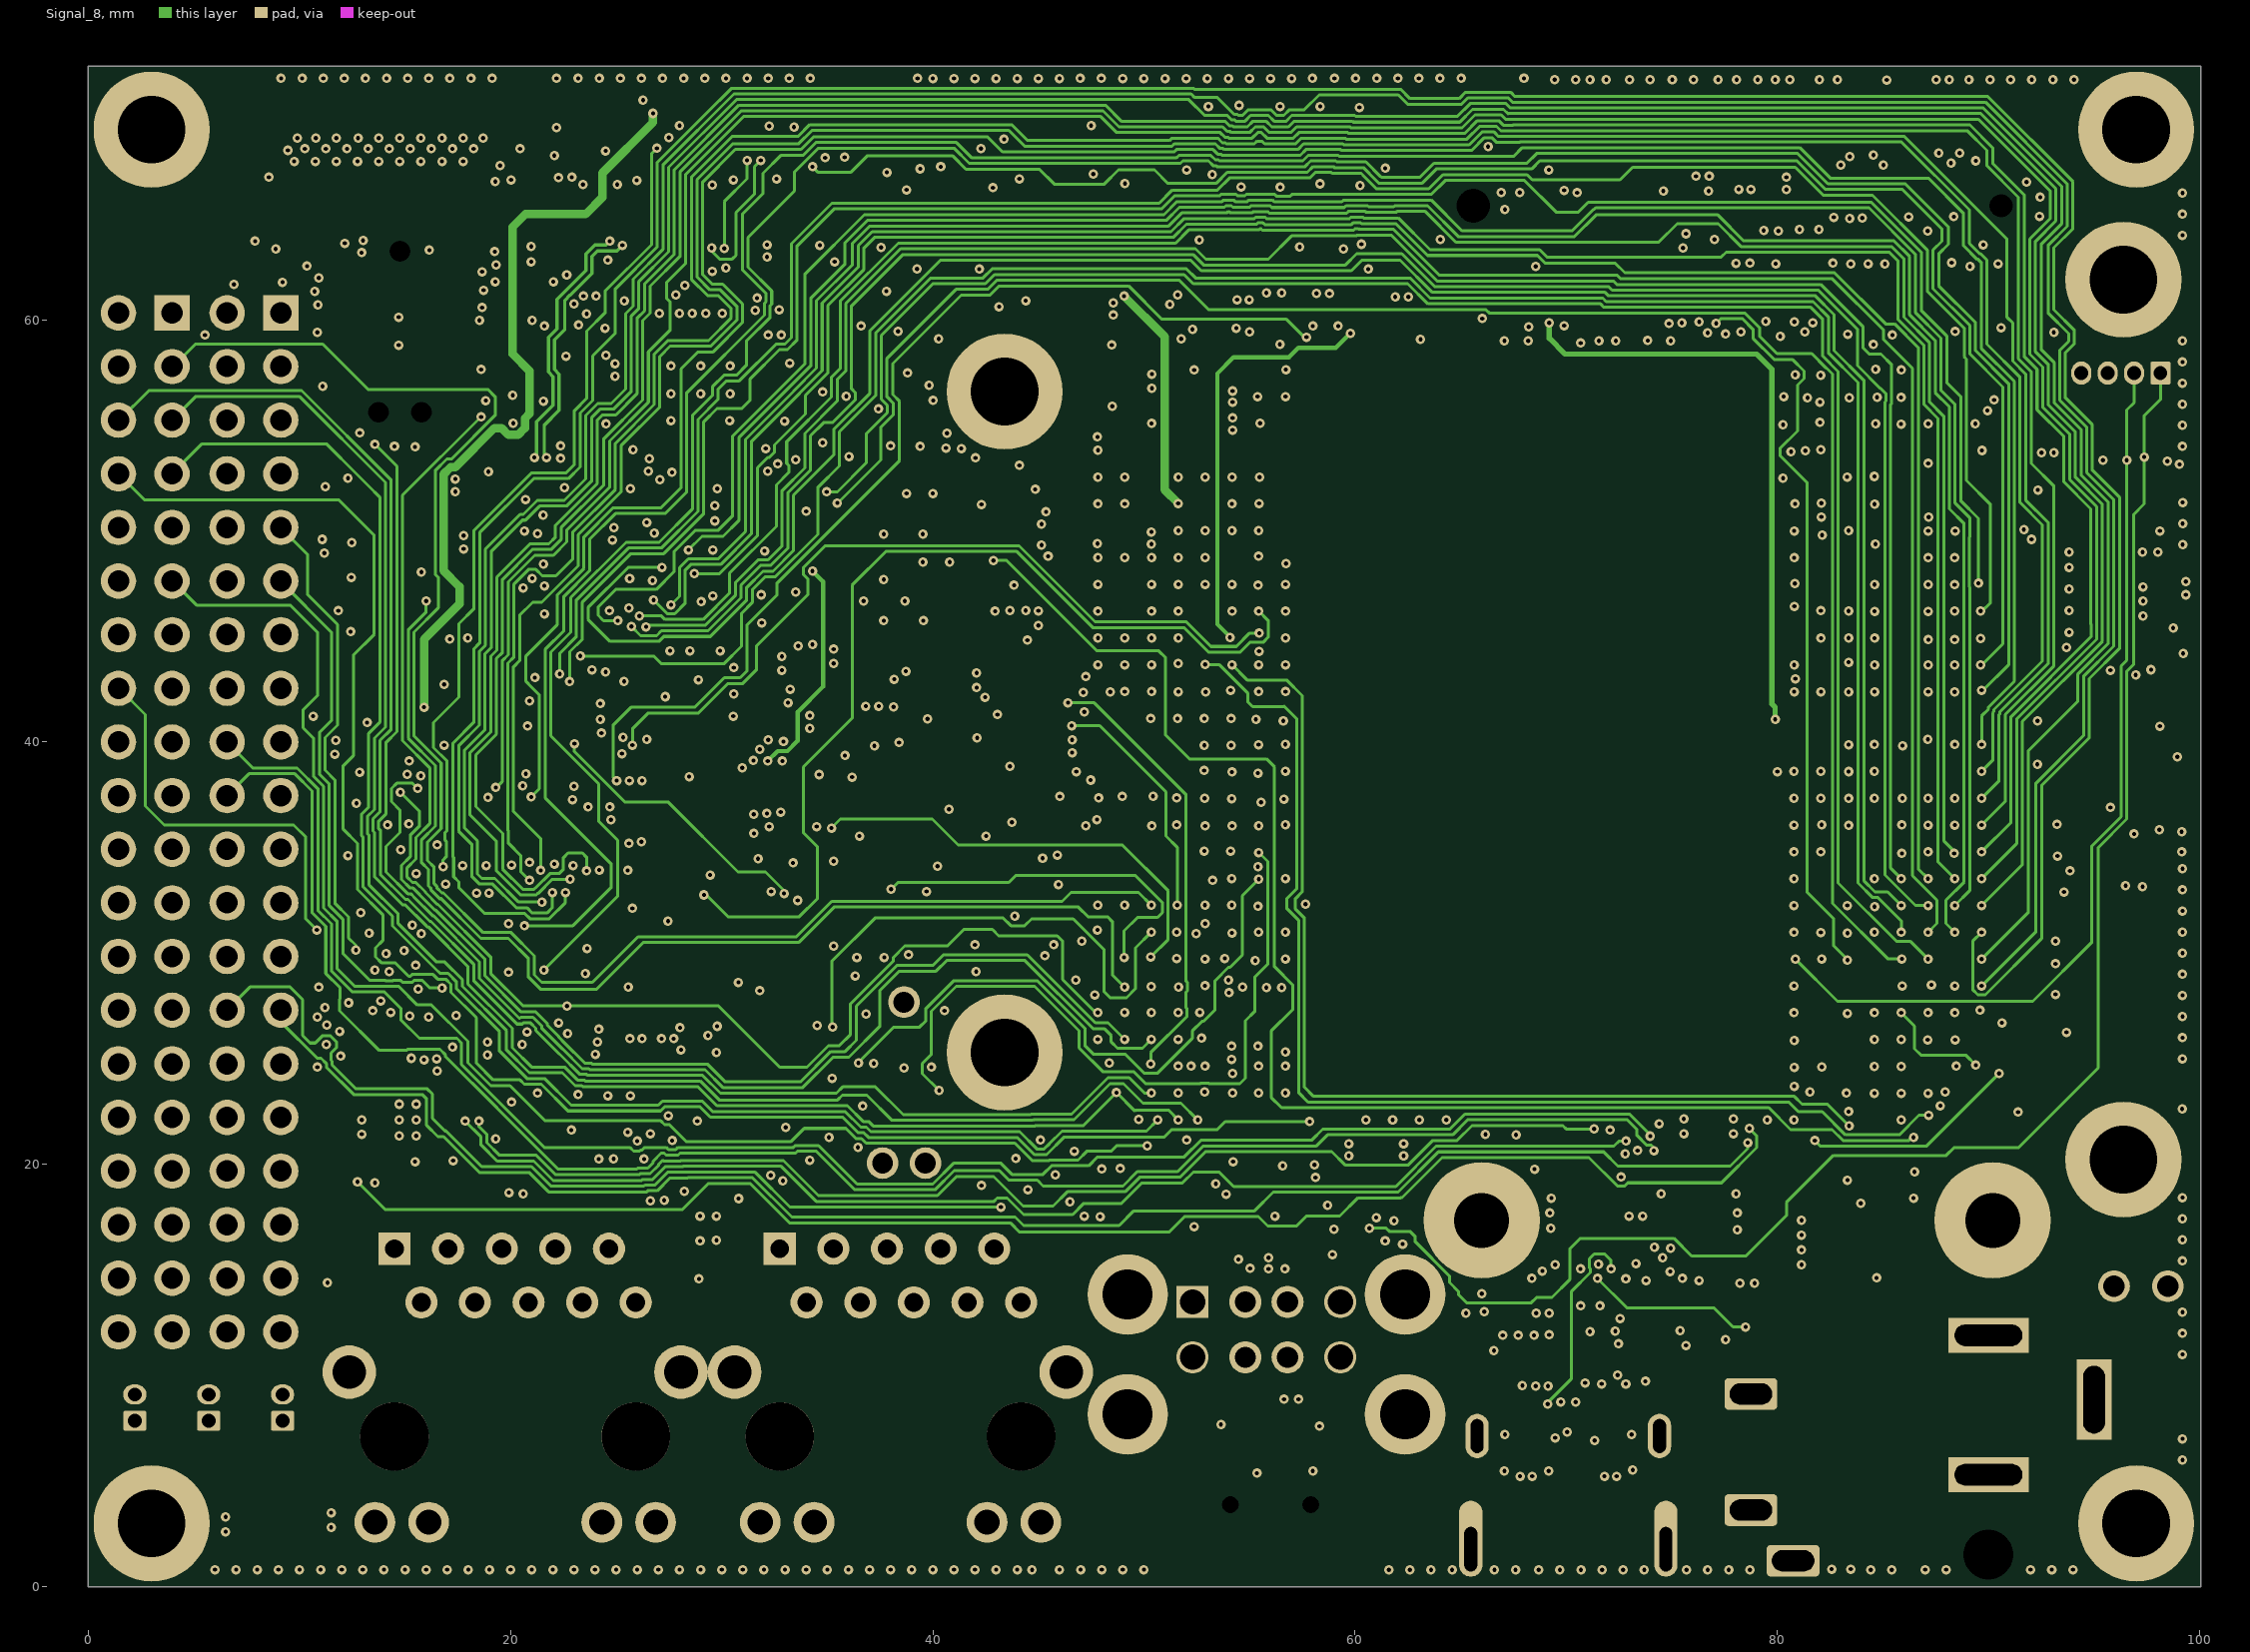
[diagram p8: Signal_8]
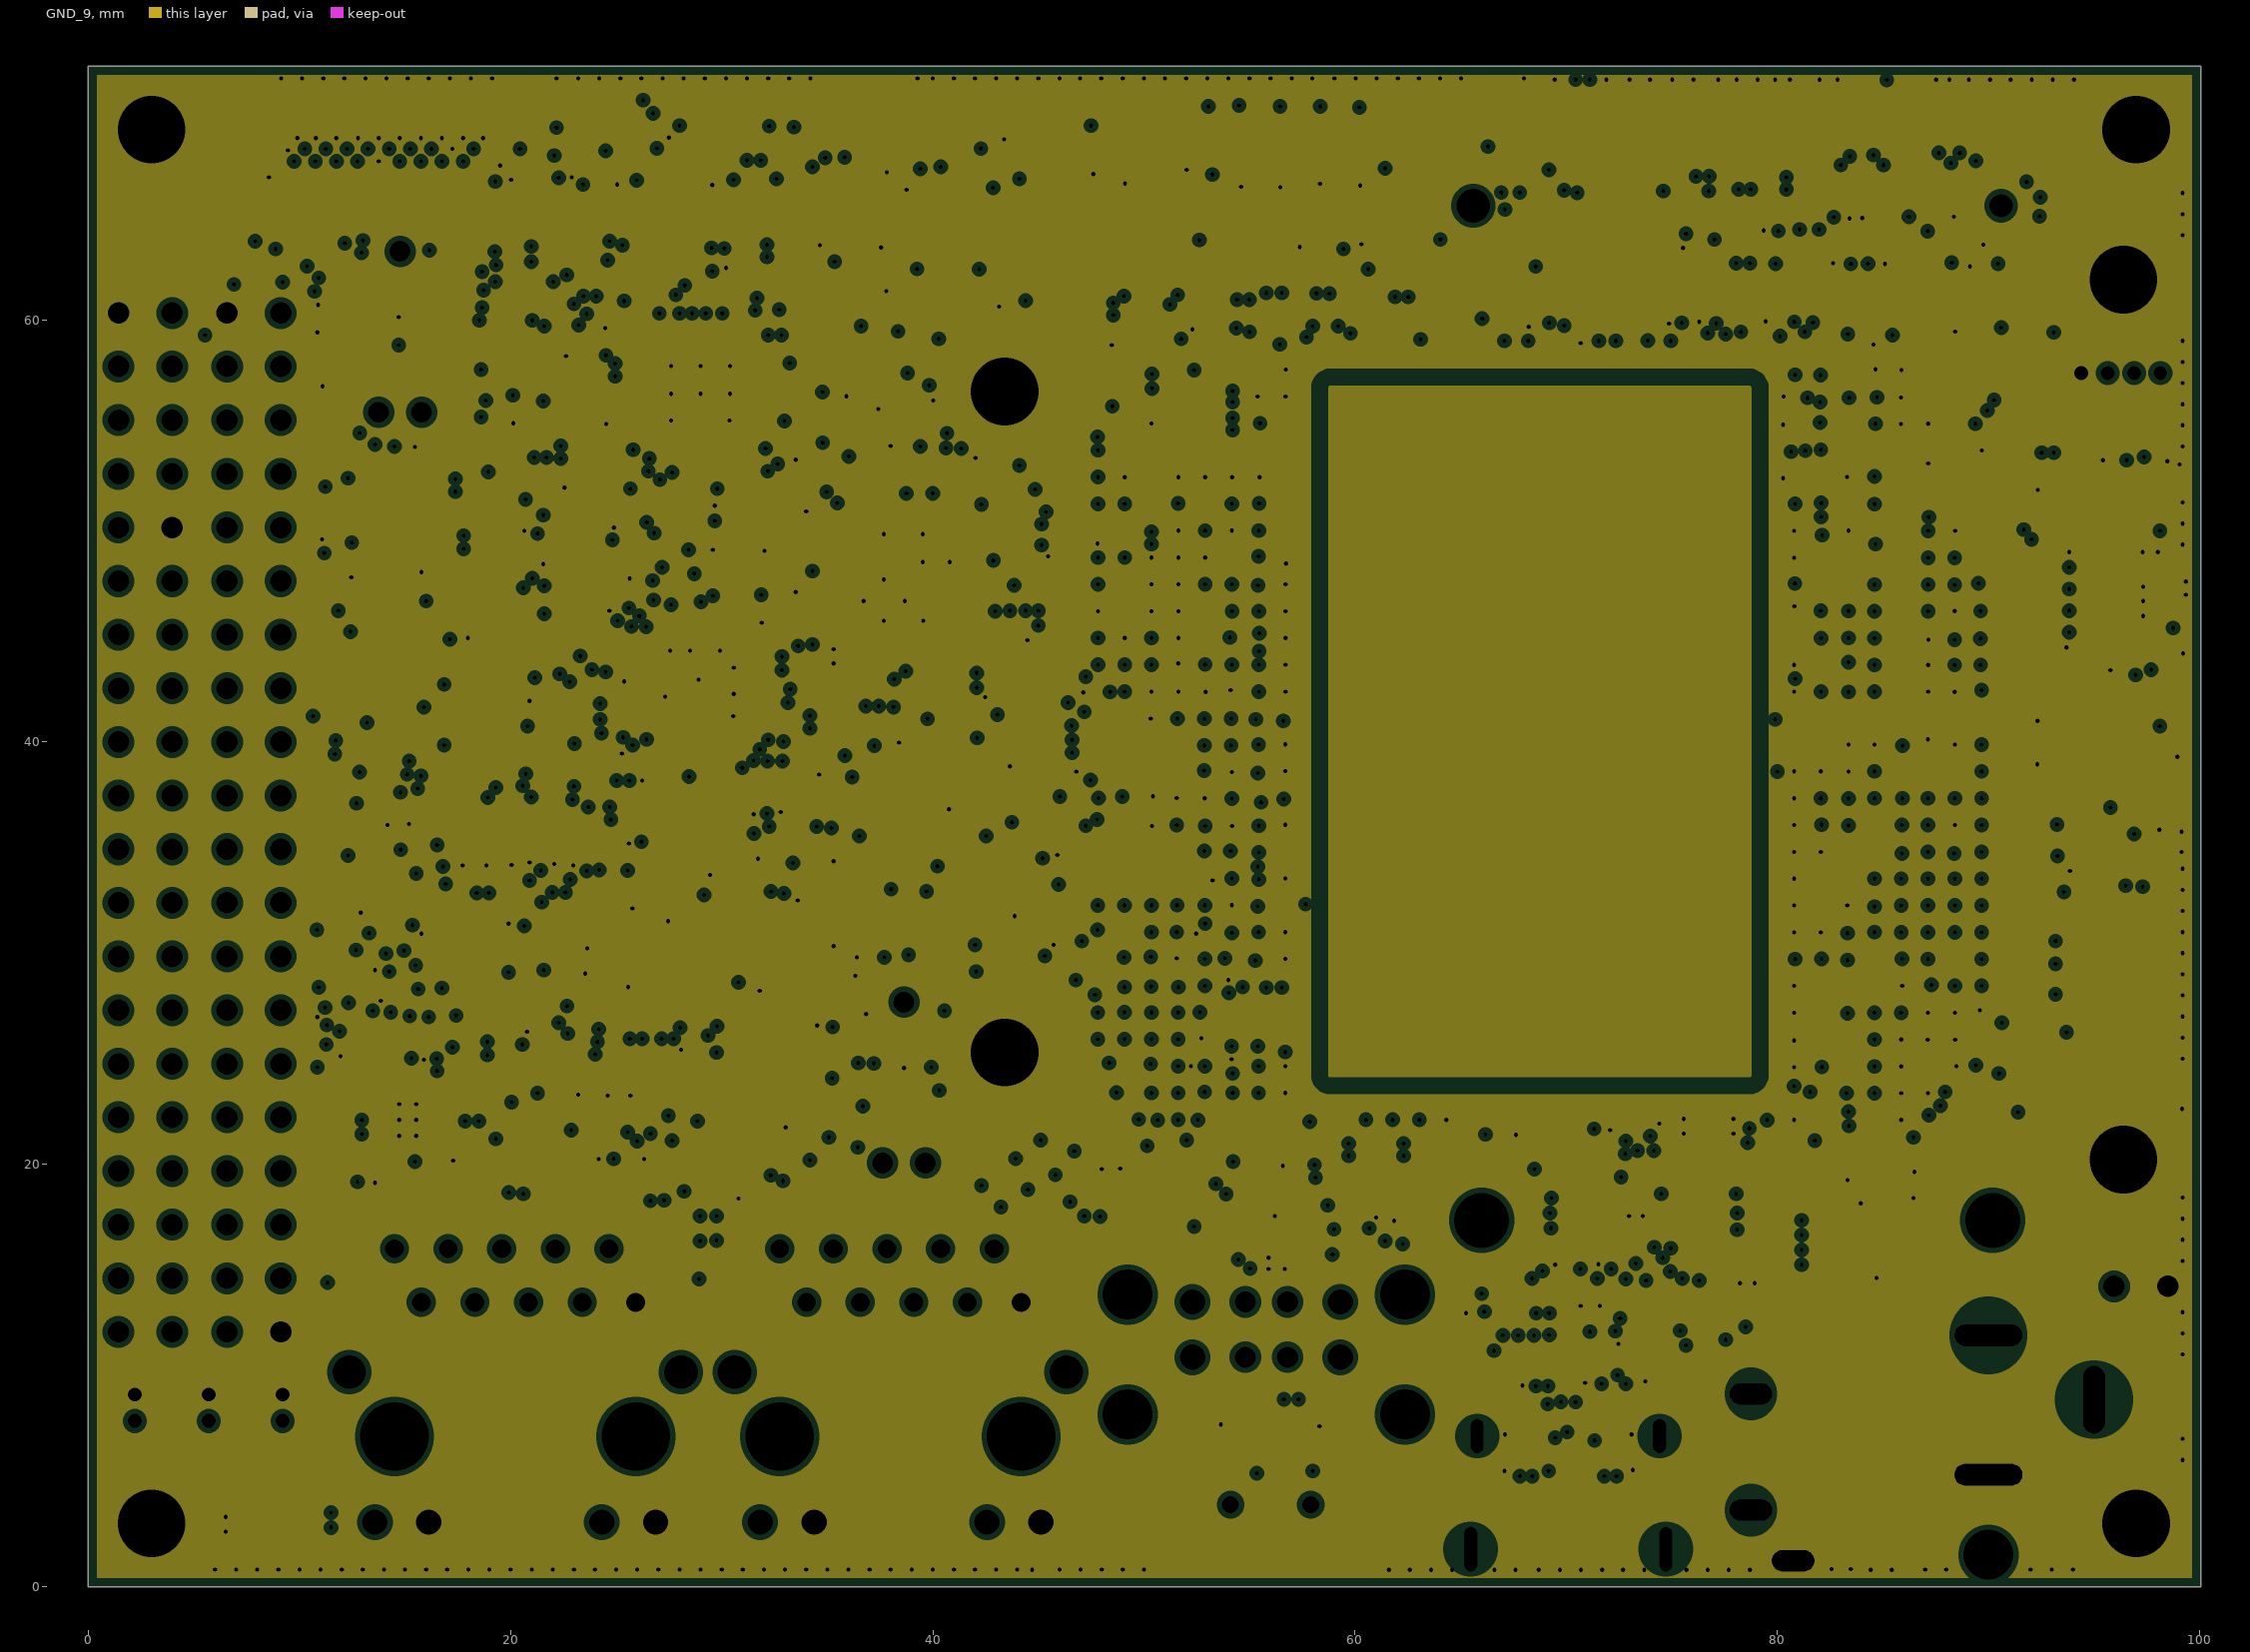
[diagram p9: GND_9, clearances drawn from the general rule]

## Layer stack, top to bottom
Top Solder: solder mask 0.0178, Dielectric, Dk 0
Top: signal copper 0.0518
Dielectric1: prepreg 0.0968, 2313, Dk 4.3
GND_2: plane copper 0.0127, net GND
Dielectric2: core 0.127, CORE, Dk 4.15
Signal_3: signal copper 0.0127
Dielectric3: prepreg 0.1123, 2116H, Dk 4.2
Signal_4: signal copper 0.0127
Dielectric 13: core 0.127, CORE, Dk 4.15
PWR_5: plane copper 0.0127, net (Multiple Nets)
Dielectric6: prepreg 0.3612, 7628 x 2, Dk 4.6
GND_6: plane copper 0.0127, net GND
Dielectric9: core 0.127, CORE, Dk 4.15
Signal_7: signal copper 0.0127
Dielectric10: prepreg 0.1123, 2116H, Dk 4.2
Signal_8: signal copper 0.0127
Dielectric 12: core 0.127, CORE, Dk 4.15
GND_9: plane copper 0.0127, net GND
Dielectric11: prepreg 0.0968, 2313, Dk 4.3
Bottom: signal copper 0.0518
Bottom Solder: solder mask 0.0178, Dielectric, Dk 0

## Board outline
0,0 0,72 100.05,72 100.05,0

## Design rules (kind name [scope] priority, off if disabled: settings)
AssemblyTestPointUsage [All] p0 off: scope1count=1 scope1_0_kind=Board scope1_0_value=Board scope2count=1 scope2_0_kind=Board scope2_0_value=Board commentlength=0
AssemblyTestPointUsage [All] p1 off: valid=2
AssemblyTestpoint [All] p0 off: scope1count=1 scope1_0_kind=Board scope1_0_value=Board scope2count=1 scope2_0_kind=Board scope2_0_value=Board commentlength=0
AssemblyTestpoint [All] p1 off: testpointundercomponent=TRUE minsize=1.016 maxsize=2.54 preferedsize=1.524 minholesize=0 maxholesize=1.016 preferedholesize=0.813 testpointgrid=0.025 usegrid=TRUE gridtolerance=0 allowsidetop=TRUE allowsidebottom=TRUE
BoardOutlineClearance [All] p0 off: scope1count=1 scope1_0_kind=Board scope1_0_value=Board scope2count=1 scope2_0_kind=Board scope2_0_value=Board commentlength=50 gap=0.4 // Protel DXP Scope 1 Expression Was: INNET ('*')
BoardOutlineClearance [INNET ('*')] p1: gap=0.4 ignorepadtopadclearanceinfootprint=FALSE except(0.34: Via-OutlineEdge)
Clearance "Global Clearance" [All] p0: scope1count=1 scope1_0_kind=Board scope1_0_value=Board scope2count=1 scope2_0_kind=Board scope2_0_value=Board commentlength=0 gap=0.127
Clearance Clearance_pad-pad [All] p0 off: scope1count=1 scope1_0_kind=Board scope1_0_value=Board scope2count=1 scope2_0_kind=Board scope2_0_value=Board commentlength=44 gap=0.3 // Protel DXP Scope 2 Expression Was: ispad
Clearance Clearance_via-pad [All] p0 off: scope1count=1 scope1_0_kind=Board scope1_0_value=Board scope2count=1 scope2_0_kind=Board scope2_0_value=Board commentlength=44 gap=0 // Protel DXP Scope 2 Expression Was: ispad
Clearance Clearance_Poly [All] p0 off: scope1count=1 scope1_0_kind=Board scope1_0_value=Board scope2count=1 scope2_0_kind=Board scope2_0_value=Board commentlength=45 gap=0.2 // Protel DXP Scope 1 Expression Was: InPoly
Clearance "2mm thru hole to SMT" [All] p0 off: scope1count=1 scope1_0_kind=Board scope1_0_value=Board scope2count=1 scope2_0_kind=Board scope2_0_value=Board commentlength=176 gap=2 // Protel DXP Scope 2 Expression Was: IsThruPin And InThruComponent  And Not ((ObjectKind = 'Pad') And (Layer = 'MultiLayer') And (Net = 'No Net') And (PadIsPlated = 'False'))
Clearance "2mm thru hole to SMT" [IsPad and inSMTComponent and onBottom vs IsThruPin And InThruComponent  And Not ((ObjectKind = 'Pad') And (Layer = 'MultiLayer') And (Net = 'No Net') And (PadIsPlated = 'False'))] p1: gap=2 ignorepadtopadclearanceinfootprint=FALSE except(0.2: Arc-Hole Track-Hole SMDPad-Hole THPad-Hole Via-Hole Fill-Hole Poly-Hole Region-Hole Text-Hole)
Clearance Clearance_Poly [InPoly] p2: gap=0.2 ignorepadtopadclearanceinfootprint=FALSE
Clearance Clearance_via-pad [isvia vs ispad] p3: gap=0 ignorepadtopadclearanceinfootprint=FALSE
Clearance Clearance_pad-pad [ispad vs ispad] p4: gap=0.3 ignorepadtopadclearanceinfootprint=TRUE except(0.2: Arc-Hole Track-Hole SMDPad-Hole THPad-Hole Via-Hole Fill-Hole Poly-Hole Region-Hole Text-Hole)
Clearance "Global Clearance" [All] p5: gap=0.127 ignorepadtopadclearanceinfootprint=FALSE except(0.2: Arc-Hole Track-Hole SMDPad-Hole THPad-Hole Via-Hole Fill-Hole Poly-Hole Region-Hole Text-Hole)
ComponentClearance [All] p0 off: scope1count=1 scope1_0_kind=Board scope1_0_value=Board scope2count=1 scope2_0_kind=Board scope2_0_value=Board commentlength=0 gap=0.25 collisioncheckmode=3
ComponentClearance [All] p1 off: gap=0.25 collisioncheckmode=3 verticalgap=0.25 showdistances=TRUE
DiffPairsRouting "ICD Stackup Planner 85ohm" [All] p0 off: scope1count=1 scope1_0_kind=Board scope1_0_value=Board scope2count=1 scope2_0_kind=Board scope2_0_value=Board commentlength=73 // Protel DXP Scope 1 Expression Was: InDifferentialPairClass('85_Ohms')
DiffPairsRouting "ICD Stackup Planner 90ohm" [All] p0 off: scope1count=1 scope1_0_kind=Board scope1_0_value=Board scope2count=1 scope2_0_kind=Board scope2_0_value=Board commentlength=73 // Protel DXP Scope 1 Expression Was: InDifferentialPairClass('90_Ohms')
DiffPairsRouting "ICD Stackup Planner 100ohm" [All] p0 off: scope1count=1 scope1_0_kind=Board scope1_0_value=Board scope2count=1 scope2_0_kind=Board scope2_0_value=Board commentlength=74 // Protel DXP Scope 1 Expression Was: InDifferentialPairClass('100_Ohms')
DiffPairsRouting "ICD Stackup Planner 100ohm" [InDifferentialPairClass('100_Ohms')] p1: maxlimit=0.229 minlimit=0.206 mostfreqgap=0.206 toplayer_mingap=0.229 toplayer_prefgap=0.229 toplayer_minwidth=0.102 toplayer_maxwidth=0.102 toplayer_prefwidth=0.102 midlayer1_maxgap=0.206 midlayer1_minwidth=0.124 midlayer1_maxwidth=0.124 midlayer1_prefwidth=0.124 midlayer2_maxgap=0.206 midlayer2_minwidth=0.124 midlayer2_maxwidth=0.124 midlayer2_prefwidth=0.124 midlayer3_maxgap=0.206 midlayer3_minwidth=0.124 midlayer3_maxwidth=0.124 midlayer3_prefwidth=0.124 midlayer4_maxgap=0.206 midlayer4_minwidth=0.124 midlayer4_maxwidth=0.124 midlayer4_prefwidth=0.124 bottomlayer_mingap=0.229 bottomlayer_prefgap=0.229 bottomlayer_minwidth=0.102 bottomlayer_maxwidth=0.102 bottomlayer_prefwidth=0.102 maxuncoupledlength=20
DiffPairsRouting "ICD Stackup Planner 90ohm" [InDifferentialPairClass('90_Ohms')] p2: maxlimit=0.236 minlimit=0.211 mostfreqgap=0.211 toplayer_mingap=0.236 toplayer_prefgap=0.236 toplayer_minwidth=0.132 toplayer_maxwidth=0.132 toplayer_prefwidth=0.132 midlayer1_maxgap=0.211 midlayer1_minwidth=0.157 midlayer1_maxwidth=0.157 midlayer1_prefwidth=0.157 midlayer2_maxgap=0.211 midlayer2_minwidth=0.157 midlayer2_maxwidth=0.157 midlayer2_prefwidth=0.157 midlayer3_maxgap=0.211 midlayer3_minwidth=0.157 midlayer3_maxwidth=0.157 midlayer3_prefwidth=0.157 midlayer4_maxgap=0.211 midlayer4_minwidth=0.157 midlayer4_maxwidth=0.157 midlayer4_prefwidth=0.157 bottomlayer_mingap=0.236 bottomlayer_prefgap=0.236 bottomlayer_minwidth=0.132 bottomlayer_maxwidth=0.132 bottomlayer_prefwidth=0.132 maxuncoupledlength=20
DiffPairsRouting "ICD Stackup Planner 85ohm" [InDifferentialPairClass('85_Ohms')] p3: maxlimit=0.218 minlimit=0.193 mostfreqgap=0.193 toplayer_mingap=0.218 toplayer_prefgap=0.218 toplayer_minwidth=0.15 toplayer_maxwidth=0.15 toplayer_prefwidth=0.15 midlayer1_maxgap=0.193 midlayer1_minwidth=0.175 midlayer1_maxwidth=0.175 midlayer1_prefwidth=0.175 midlayer2_maxgap=0.193 midlayer2_minwidth=0.175 midlayer2_maxwidth=0.175 midlayer2_prefwidth=0.175 midlayer3_maxgap=0.193 midlayer3_minwidth=0.175 midlayer3_maxwidth=0.175 midlayer3_prefwidth=0.175 midlayer4_maxgap=0.193 midlayer4_minwidth=0.175 midlayer4_maxwidth=0.175 midlayer4_prefwidth=0.175 bottomlayer_mingap=0.218 bottomlayer_prefgap=0.218 bottomlayer_minwidth=0.15 bottomlayer_maxwidth=0.15 bottomlayer_prefwidth=0.15 maxuncoupledlength=20
FabricationTestPointUsage TestPointUsage [All] p0 off: scope1count=1 scope1_0_kind=Board scope1_0_value=Board scope2count=1 scope2_0_kind=Board scope2_0_value=Board commentlength=0 valid=2 allowmultiple=FALSE
FabricationTestPointUsage TestPointUsage [All] p1 off: valid=2 allowmultiple=FALSE
FabricationTestpoint Testpoint [All] p0 off: scope1count=1 scope1_0_kind=Board scope1_0_value=Board scope2count=1 scope2_0_kind=Board scope2_0_value=Board commentlength=0 side=3 testpointundercomponent=TRUE minsize=1.016 maxsize=2.54 preferedsize=1.524 minholesize=0 maxholesize=1.016 preferedholesize=0.813 testpointgrid=0.025
FabricationTestpoint Testpoint [All] p1 off: side=3 testpointundercomponent=TRUE minsize=1.016 maxsize=2.54 preferedsize=1.524 minholesize=0 maxholesize=1.016 preferedholesize=0.813 testpointgrid=0.025 allowsidetop=TRUE allowsidebottom=TRUE usegrid=TRUE gridtolerance=0
FanoutControl Fanout_Default [All] p0: scope1count=1 scope1_0_kind=Board scope1_0_value=Board scope2count=1 scope2_0_kind=Board scope2_0_value=Board commentlength=30 // Fanout_Default (Default Rule)
FanoutControl Fanout_Small [All] p0 off: scope1count=1 scope1_0_kind=Board scope1_0_value=Board scope2count=1 scope2_0_kind=Board scope2_0_value=Board commentlength=84 // Protel DXP Scope 1 Expression Was: (CompPinCount < 5)   Fanout_Small (Default Rule)
FanoutControl Fanout_SOIC [All] p0 off: scope1count=1 scope1_0_kind=Board scope1_0_value=Board scope2count=1 scope2_0_kind=Board scope2_0_value=Board commentlength=71 // Protel DXP Scope 1 Expression Was: IsSOIC   Fanout_SOIC (Default Rule)
FanoutControl Fanout_LCC [All] p0 off: scope1count=1 scope1_0_kind=Board scope1_0_value=Board scope2count=1 scope2_0_kind=Board scope2_0_value=Board commentlength=69 // Protel DXP Scope 1 Expression Was: IsLCC   Fanout_LCC (Default Rule)
FanoutControl Fanout_BGA [All] p0 off: scope1count=1 scope1_0_kind=Board scope1_0_value=Board scope2count=1 scope2_0_kind=Board scope2_0_value=Board commentlength=69 // Protel DXP Scope 1 Expression Was: IsBGA   Fanout_BGA (Default Rule)
FanoutControl Fanout_BGA [IsBGA] p1 off: bgadir=Out bgaviamode=Centered fanoutstyle=Auto fanoutdirection=Alternating viagrid=0.025 // Fanout_BGA (Default Rule)
FanoutControl Fanout_Small [(CompPinCount < 5)] p4: bgadir=Out bgaviamode=Closest fanoutstyle=Auto fanoutdirection=OutThenIn viagrid=0.025 // Fanout_Small (Default Rule)
Height [All] p0: scope1count=1 scope1_0_kind=Board scope1_0_value=Board scope2count=1 scope2_0_kind=Board scope2_0_value=Board commentlength=0
HoleSize [All] p0: scope1count=1 scope1_0_kind=Board scope1_0_value=Board scope2count=1 scope2_0_kind=Board scope2_0_value=Board commentlength=0 absolutevalues=TRUE maxlimit=3.3 minlimit=0.2 maxpercent=80.000 minpercent=20.000
HoleSize [All] p1: absolutevalues=TRUE maxlimit=3.3 minlimit=0.2 maxpercent=80.000 minpercent=20.000
HoleToHoleClearance [All] p0: scope1count=1 scope1_0_kind=Board scope1_0_value=Board scope2count=1 scope2_0_kind=Board scope2_0_value=Board commentlength=0
HoleToHoleClearance [All] p1: gap=0.25 allowstackedmicrovias=TRUE
LayerPairs [All] p0: scope1count=1 scope1_0_kind=Board scope1_0_value=Board scope2count=1 scope2_0_kind=Board scope2_0_value=Board commentlength=0 enforce=TRUE
MatchedLengths [All] p0 off: scope1count=1 scope1_0_kind=Board scope1_0_value=Board scope2count=1 scope2_0_kind=Board scope2_0_value=Board commentlength=88 tolerance=0.1 amplitude=5.08 gap=0.508 style=90-Degree // Protel DXP Scope 1 Expression Was: InDifferentialPairClass('All Differential Pairs')
MatchedLengths MatchedLengths_MIPI_CSI0_1 [All] p0 off: scope1count=1 scope1_0_kind=Board scope1_0_value=Board scope2count=1 scope2_0_kind=Board scope2_0_value=Board commentlength=65 tolerance=2.5 amplitude=5.08 gap=0.508 style=90-Degree // Protel DXP Scope 1 Expression Was: InxSignalClass('MIPI_CSI')
MatchedLengths MatchedLengths_MIPI_CSI_GROUP [All] p0 off: scope1count=1 scope1_0_kind=Board scope1_0_value=Board scope2count=1 scope2_0_kind=Board scope2_0_value=Board commentlength=60 tolerance=2.5 amplitude=5.08 gap=0.508 style=90-Degree // Protel DXP Scope 1 Expression Was: InxSignalClass('CSI')
MatchedLengths MatchedLengths_MIPI_DSI1 [All] p0 off: scope1count=1 scope1_0_kind=Board scope1_0_value=Board scope2count=1 scope2_0_kind=Board scope2_0_value=Board commentlength=66 tolerance=2.5 amplitude=5.08 gap=0.508 style=90-Degree // Protel DXP Scope 1 Expression Was: InxSignalClass('MIPI_DSI1')
MatchedLengths MatchedLengths_MIPI_DSI0 [All] p0 off: scope1count=1 scope1_0_kind=Board scope1_0_value=Board scope2count=1 scope2_0_kind=Board scope2_0_value=Board commentlength=66 tolerance=2.5 amplitude=5.08 gap=0.508 style=90-Degree // Protel DXP Scope 1 Expression Was: InxSignalClass('MIPI_DSI0')
MatchedLengths MatchedLengths_MIPI_CSI [All] p0 off: scope1count=1 scope1_0_kind=Board scope1_0_value=Board scope2count=1 scope2_0_kind=Board scope2_0_value=Board commentlength=69 tolerance=2.5 amplitude=5.08 gap=0.508 style=90-Degree // Protel DXP Scope 1 Expression Was: InDifferentialPairClass('CSI')
MatchedLengths MatchedLengths_ETH2 [All] p0 off: scope1count=1 scope1_0_kind=Board scope1_0_value=Board scope2count=1 scope2_0_kind=Board scope2_0_value=Board commentlength=70 tolerance=2.5 amplitude=5.08 gap=0.508 style=90-Degree // Protel DXP Scope 1 Expression Was: InDifferentialPairClass('ETH2')
MatchedLengths MatchedLengths_ETH1 [All] p0 off: scope1count=1 scope1_0_kind=Board scope1_0_value=Board scope2count=1 scope2_0_kind=Board scope2_0_value=Board commentlength=70 tolerance=2.5 amplitude=5.08 gap=0.508 style=90-Degree // Protel DXP Scope 1 Expression Was: InDifferentialPairClass('ETH1')
MatchedLengths MatchedLengths_ETH1 [InDifferentialPairClass('ETH1')] p1: tolerance=2.5 checknetsindiffpair=FALSE checkdiffpairvsdiffpair=TRUE checkxsignals=TRUE checkothers=TRUE
MatchedLengths MatchedLengths_ETH2 [InDifferentialPairClass('ETH2')] p2: tolerance=2.5 checknetsindiffpair=FALSE checkdiffpairvsdiffpair=TRUE checkxsignals=TRUE checkothers=TRUE
MatchedLengths MatchedLengths_MIPI_CSI [InDifferentialPairClass('CSI')] p3: tolerance=2.5 checknetsindiffpair=FALSE checkdiffpairvsdiffpair=TRUE checkxsignals=TRUE checkothers=TRUE
MatchedLengths MatchedLengths_MIPI_DSI0 [InxSignalClass('MIPI_DSI0')] p4: tolerance=2.5 checknetsindiffpair=FALSE checkdiffpairvsdiffpair=TRUE checkxsignals=TRUE checkothers=TRUE
MatchedLengths MatchedLengths_MIPI_DSI1 [InxSignalClass('MIPI_DSI1')] p5: tolerance=2.5 checknetsindiffpair=FALSE checkdiffpairvsdiffpair=TRUE checkxsignals=TRUE checkothers=TRUE
MatchedLengths MatchedLengths_MIPI_CSI_GROUP [InxSignalClass('CSI')] p6: tolerance=2.5 checknetsindiffpair=FALSE checkdiffpairvsdiffpair=TRUE checkxsignals=TRUE checkothers=TRUE
MatchedLengths MatchedLengths_MIPI_CSI0_1 [InxSignalClass('MIPI_CSI')] p7: tolerance=2.5 checknetsindiffpair=FALSE checkdiffpairvsdiffpair=TRUE checkxsignals=TRUE checkothers=TRUE
MatchedLengths [InDifferentialPairClass('All Differential Pairs')] p8: tolerance=0.1 checknetsindiffpair=TRUE checkdiffpairvsdiffpair=FALSE checkxsignals=FALSE checkothers=FALSE
MinimumAnnularRing [All] p0 off: scope1count=1 scope1_0_kind=Board scope1_0_value=Board scope2count=1 scope2_0_kind=Board scope2_0_value=Board commentlength=0 minimumring=0.127
MinimumAnnularRing [All] p1 off: minimumring=0.127
MinimumSolderMaskSliver [All] p0 off: scope1count=1 scope1_0_kind=Board scope1_0_value=Board scope2count=1 scope2_0_kind=Board scope2_0_value=Board commentlength=0
MinimumSolderMaskSliver [All] p1 off: minsoldermaskwidth=0.1
NetAntennae [All] p0: scope1count=1 scope1_0_kind=Board scope1_0_value=Board scope2count=1 scope2_0_kind=Board scope2_0_value=Board commentlength=0
PasteMaskExpansion [All] p0: scope1count=1 scope1_0_kind=Board scope1_0_value=Board scope2count=1 scope2_0_kind=Board scope2_0_value=Board commentlength=0 expansion=0
PlaneClearance [All] p0: scope1count=1 scope1_0_kind=Board scope1_0_value=Board scope2count=1 scope2_0_kind=Board scope2_0_value=Board commentlength=0 clearance=0.25
PlaneClearance "3V3 PlaneClearance" [All] p0 off: scope1count=1 scope1_0_kind=Board scope1_0_value=Board scope2count=1 scope2_0_kind=Board scope2_0_value=Board commentlength=70 clearance=0.25 // Protel DXP Scope 1 Expression Was: (InNamedPolygon('Layer 7 3V3'))
PlaneClearance "3V3 PlaneClearance" [(InNamedPolygon('Layer 7 3V3'))] p1: clearance=0.25
PlaneClearance [All] p2: clearance=0.25
PlaneConnect [All] p0: scope1count=1 scope1_0_kind=Board scope1_0_value=Board scope2count=1 scope2_0_kind=Board scope2_0_value=Board commentlength=0 planeconnectstyle=Relief reliefexpansion=0.2 reliefentries=4 reliefconductorwidth=0.25 reliefairgap=0.2
PlaneConnect "Via_ Direct_Connect_to_Plane" [All] p0 off: scope1count=1 scope1_0_kind=Board scope1_0_value=Board scope2count=1 scope2_0_kind=Board scope2_0_value=Board commentlength=44 planeconnectstyle=Direct reliefexpansion=0.508 reliefentries=4 reliefconductorwidth=0.254 reliefairgap=0.254 // Protel DXP Scope 1 Expression Was: IsVia
PlaneConnect "Via_ Direct_Connect_to_Plane" [IsVia] p1: planeconnectstyle=Direct reliefexpansion=0.508 reliefentries=4 reliefconductorwidth=0.254 reliefairgap=0.254
PlaneConnect [All] p2: planeconnectstyle=Relief reliefexpansion=0.2 reliefentries=4 reliefconductorwidth=0.25 reliefairgap=0.2
PolygonConnect [All] p0: scope1count=1 scope1_0_kind=Board scope1_0_value=Board scope2count=1 scope2_0_kind=Board scope2_0_value=Board commentlength=0 connectstyle=Relief reliefconductorwidth=0.25 reliefentries=4 polygonreliefangle="90 Angle"
PolygonConnect "Polygon To Via" [All] p0 off: scope1count=1 scope1_0_kind=Board scope1_0_value=Board scope2count=1 scope2_0_kind=Board scope2_0_value=Board commentlength=44 connectstyle=Direct reliefconductorwidth=0.254 reliefentries=4 polygonreliefangle="90 Angle" // Protel DXP Scope 1 Expression Was: IsVia
PolygonConnect Polysolid [All] p0 off: scope1count=1 scope1_0_kind=Board scope1_0_value=Board scope2count=1 scope2_0_kind=Board scope2_0_value=Board commentlength=66 connectstyle=Direct reliefconductorwidth=0.254 reliefentries=4 polygonreliefangle="90 Angle" // Protel DXP Scope 2 Expression Was: IsnamedPolygon('Polysolid')
PolygonConnect Polysolid [All vs IsnamedPolygon('Polysolid')] p1: connectstyle=Direct reliefconductorwidth=0.254 reliefentries=4 polygonreliefangle="90 Angle" airgapwidth=0.254
PolygonConnect "Polygon To Via" [IsVia] p2: connectstyle=Direct reliefconductorwidth=0.254 reliefentries=4 polygonreliefangle="90 Angle" airgapwidth=0.254
PolygonConnect [All] p3: connectstyle=Relief reliefconductorwidth=0.25 reliefentries=4 polygonreliefangle="90 Angle" airgapwidth=0.2
RoutingCorners [All] p0: scope1count=1 scope1_0_kind=Board scope1_0_value=Board scope2count=1 scope2_0_kind=Board scope2_0_value=Board commentlength=0 cornerstyle=45-Degree minsetback=2 maxsetback=2
RoutingCorners [All] p1: cornerstyle=45-Degree minsetback=2 maxsetback=2
RoutingLayers [All] p0: scope1count=1 scope1_0_kind=Board scope1_0_value=Board scope2count=1 scope2_0_kind=Board scope2_0_value=Board commentlength=0 top layer=Automatic mid layer 1=Automatic mid layer 2=Automatic mid layer 3=Automatic mid layer 4=Automatic bottom layer=Automatic
RoutingPriority [All] p0: scope1count=1 scope1_0_kind=Board scope1_0_value=Board scope2count=1 scope2_0_kind=Board scope2_0_value=Board commentlength=0
RoutingTopology [All] p0: scope1count=1 scope1_0_kind=Board scope1_0_value=Board scope2count=1 scope2_0_kind=Board scope2_0_value=Board commentlength=0 topology=Shortest
RoutingVias "ICD Stackup Planner PTH Via 1" [All] p0: scope1count=1 scope1_0_kind=Board scope1_0_value=Board scope2count=1 scope2_0_kind=Board scope2_0_value=Board commentlength=0 holewidth=0.25 width=0.56 viastyle="Through Hole" minholewidth=0.2 minwidth=0.457 maxholewidth=1 maxwidth=1.5
RoutingVias "ICD Stackup Planner PTH Via 1" [All] p1: holewidth=0.25 width=0.56 viastyle="Through Hole" minholewidth=0.2 minwidth=0.457 maxholewidth=1 maxwidth=1.5 useviatemplates=TRUE viatemplateguid#1={D0C2CE42-2BFB-46EA-9632-C742B0E0D7E2} viatemplatename#1=v45h20m0mx0
SMDNeckDown [All] p0: scope1count=1 scope1_0_kind=Board scope1_0_value=Board scope2count=1 scope2_0_kind=Board scope2_0_value=Board commentlength=0 percent=100.000
SMDNeckDown [All] p1: percent=100.000
ShortCircuit [All] p0: scope1count=1 scope1_0_kind=Board scope1_0_value=Board scope2count=1 scope2_0_kind=Board scope2_0_value=Board commentlength=0 allowed=FALSE
SilkToBoardRegionClearance [All] p0: scope1count=1 scope1_0_kind=Board scope1_0_value=Board scope2count=1 scope2_0_kind=Board scope2_0_value=Board commentlength=0
SilkToSilkClearance [All] p0 off: scope1count=1 scope1_0_kind=Board scope1_0_value=Board scope2count=1 scope2_0_kind=Board scope2_0_value=Board commentlength=0
SilkToSilkClearance [All] p1 off: silktosilkclearance=0.125
SilkToSolderMaskClearance SilkscreenOverComponentPads [All] p0 off: scope1count=1 scope1_0_kind=Board scope1_0_value=Board scope2count=1 scope2_0_kind=Board scope2_0_value=Board commentlength=44 // Protel DXP Scope 1 Expression Was: IsPad
SilkToSolderMaskClearance SilkscreenOverComponentPads [IsPad] p1 off: minsilkscreentomaskgap=0.125 clearancetoexposedcopper=TRUE
SolderMaskExpansion [All] p0: scope1count=1 scope1_0_kind=Board scope1_0_value=Board scope2count=1 scope2_0_kind=Board scope2_0_value=Board commentlength=0 expansion=0.05
SolderMaskExpansion [All] p1: expansion=0.05
UnRoutedNet [All] p0: scope1count=1 scope1_0_kind=Board scope1_0_value=Board scope2count=1 scope2_0_kind=Board scope2_0_value=Board commentlength=0
UnpouredPolygon [All] p0: scope1count=1 scope1_0_kind=Board scope1_0_value=Board scope2count=1 scope2_0_kind=Board scope2_0_value=Board commentlength=0
Width [All] p0: scope1count=1 scope1_0_kind=Board scope1_0_value=Board scope2count=1 scope2_0_kind=Board scope2_0_value=Board commentlength=0 maxlimit=0.158 minlimit=0.1 preferedwidth=0.142
Width "Width Power" [All] p0: scope1count=1 scope1_0_kind=NetClass scope1_0_value=Power scope2count=1 scope2_0_kind=Board scope2_0_value=Board commentlength=0 maxlimit=2 minlimit=0.127 preferedwidth=0.4
Width "Width Power" [InNetClass('Power')] p1: maxlimit=2 minlimit=0.127 preferedwidth=0.4 minimp=50.000000 maximp=50.000000 favimp=50.000000
Width [All] p2: maxlimit=0.158 minlimit=0.1 preferedwidth=0.142 toplayer_maxwidth=0.15 toplayer_prefwidth=0.127 midlayer1_minwidth=0.142 midlayer2_minwidth=0.142 midlayer3_minwidth=0.142 midlayer4_minwidth=0.142 bottomlayer_minwidth=0.127 bottomlayer_maxwidth=0.15 bottomlayer_prefwidth=0.127 minimp=50.000000 maximp=50.000000 favimp=50.000000
14 further rules are at their usual default settings.

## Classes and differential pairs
net class miniPCIe: PCIE_CLK_N PCIE_CLK_P PCIE_DIS_N PCIE_I2C_SCL PCIE_I2C_SDA PCIE_RESET_N PCIE_RX_N PCIE_RX_P PCIE_TX_N PCIE_TX_P PCIE_WAKE_N PCIECLK_N PCIECLK_P USB_PCIe_D_N USB_PCIe_D_P
net class "micro SD": NetC27_2 NetJ10_5 USDHC1_CD_B USDHC1_CLK USDHC1_CMD USDHC1_DATA0 USDHC1_DATA1 USDHC1_DATA2 USDHC1_DATA3
net class XBEE: MCA_UART2_CTS MCA_UART2_RTS MCA_UART2_RX MCA_UART2_TX XBEE_D_N XBEE_D_P XBEE_ON/SLEEP_N XBEE_RESET_N
net class SAI0: SAI0_RXD SAI0_TXC SAI0_TXD SAI0_TXFS
net class PCM: PCM_CLK PCM_IN PCM_OUT PCM_SYNC
net class RGMII2: "RGMII2_INT_ B" RGMII2_RD0 RGMII2_RD1 RGMII2_RD2 RGMII2_RD3 RGMII2_RESET_N RGMII2_RX_CTL RGMII2_RXC RGMII2_TD0 RGMII2_TD1 RGMII2_TD2 RGMII2_TD3 RGMII2_TX_CTL RGMII2_TXC RGMII_MDC_3V3 RGMII_MDIO_3V3
net class RGMII1: "RGMII1_INT_ B" RGMII1_RD0 RGMII1_RD1 RGMII1_RD2 RGMII1_RD3 RGMII1_RESET_N RGMII1_RX_CTL RGMII1_RXC RGMII1_TD0 RGMII1_TD1 RGMII1_TD2 RGMII1_TD3 RGMII1_TX_CTL RGMII1_TXC RGMII_MDC RGMII_MDC_3V3 RGMII_MDIO RGMII_MDIO_3V3
net class MIPI_CSIO: MIPI_CSI0_CLK_N MIPI_CSI0_CLK_P MIPI_CSI0_DATA0_N MIPI_CSI0_DATA0_P MIPI_CSI0_DATA1_N MIPI_CSI0_DATA1_P MIPI_CSI0_I2C0_SCL MIPI_CSI0_I2C0_SDA MIPI_CSI0_RESET_N
net class MIPI_DSI0: MIPI_DSI0_CLK_N MIPI_DSI0_CLK_P MIPI_DSI0_DATA0_N MIPI_DSI0_DATA0_P MIPI_DSI0_DATA1_N MIPI_DSI0_DATA1_P MIPI_DSI0_DATA2_N MIPI_DSI0_DATA2_P MIPI_DSI0_DATA3_N MIPI_DSI0_DATA3_P MIPI_DSI0_I2C0_SCL MIPI_DSI0_I2C0_SDA MIPI_DSI0_IRQ_N MIPI_DSI0_PWM0_OUT
net class MIPI_DSI1: MIPI_DSI1_CLK_N MIPI_DSI1_CLK_P MIPI_DSI1_DATA0_N MIPI_DSI1_DATA0_P MIPI_DSI1_DATA1_N MIPI_DSI1_DATA1_P MIPI_DSI1_DATA2_N MIPI_DSI1_DATA2_P MIPI_DSI1_DATA3_N MIPI_DSI1_DATA3_P MIPI_DSI1_I2C0_SCL MIPI_DSI1_I2C0_SDA MIPI_DSI1_IRQ_N MIPI_DSI1_PWM0_OUT
net class CSI: CSI_D00 CSI_D01 CSI_D02 CSI_D03 CSI_D04 CSI_D05 CSI_D06 CSI_D07 CSI_EN CSI_HSYNC CSI_MCLK CSI_PCLK CSI_RESET CSI_SCL CSI_SDA CSI_VSYNC
net class 5A: NetFIL1_1 VIN VIN_PROT
net class "micro SIM": PCIE_UIM_CLK PCIE_UIM_DATA PCIE_UIM_PWR PCIE_UIM_RST PCIE_UIM_VPP
component class "17 - History, Mechanicals": FIDUCIAL1 FIDUCIAL2 FIDUCIAL3 FIDUCIAL4 FIDUCIAL5 FIDUCIAL6 FIDUCIAL7 FIDUCIAL8 FIDUCIAL9 FIDUCIAL10 FIDUCIAL11 FIDUCIAL12 H1 H2 H3 H4
net class Power: 1V8 1V8_CODEC 1V8_EXT 3V3 3V3_CODEC 3V3_ETH 3V3_EXT 3V3_RF 3V3_USB 5V DVDDL1 DVDDL2 GND LDO3 NetC5_2 NetC7_1 NetC13_1 NetC13_2 NetC14_1 NetC27_2 NetC49_2 NetC56_2 NetC74_2 NetC85_2 NetC87_2 NetC90_2 NetC133_1 NetC135_2 NetC136_2 NetC142_1 NetC148_2 NetC155_1 NetC159_1 NetD2_2 NetD3_K NetD4_3 NetD8_A NetFIL1_1 NetJ14_20 NetJ16_20 NetJ18_A1 NetJ18_A4 NetJ18_B1 NetJ18_B4 NetJ23_7 NetJ28_5 NetL1_1 NetL3_1 NetL6_1 NetQ7_1 NetQ9_D NetR4_1 NetR26_1 NetR43_1 NetR45_2 NetR46_2 NetR49_1 NetR81_2 NetR219_2 NetR220_2 NetR221_2 NetR245_2 NetR247_1 NetR248_2 PCIE_VCC SHLD TCGND USBC_VBUS VCC_LICELL VCC_MCA VCC_SCU_1V8 VDDH1 VDDH2 VDDIO1 VDDIO2 VIN VIN_PROT VLDO4_1V5 VSYS XBEE_VCC
component class "06 - JTAG, SWD, MicroSD, Mini PCIe, MicroSIM": C10 C11 C12 C13 C14 C15 C16 C17 C18 C19 C20 C21 C22 C23 C24 C25 C26 C27 C28 C46 C64 C135 C136 C139 C140 CAD1 CAD2 J7 J8 J9 J10 L1 R14 R29 R30 R43 R44 R45 R46 R47 R48 R49 R50 R51 R52 R53 R54 R55 R56 R57 R58 R110 R111 R112 R117 R195 R217 R218 R236 R237 U3 U28
component class "02 - CCIMX8X Power, Control, MCA": C154 C155 C156 C157 C158 C159 C160 C161 C162 D13 R1 R2 R3 R4 R5 R6 R7 R8 R9 R205 R219 R220 R221 R230 R231 R256 R257 R258 R259 R260 TP1 TP2 TP3 TP4 TP5 TP6 TP7 TP8 TP9 TP10 U1 U32 U33
component class "05 - Power, bootstrap, reset": C1 C2 C3 C4 C5 C6 C7 C8 C9 C132 C142 C143 D3 D4 D5 D14 FIL1 J2 J3 J4 J5 J6 Q1 Q7 Q8 R13 R15 R17 R18 R19 R20 R21 R22 R23 R24 R25 R26 R27 R28 R31 R32 R33 R34 R35 R36 R37 R38 R39 R40 R41 R42 R64 R162 R213 R216 R255 S2 SW1 SW2 TP13 TP14 U2 U26 U27
component class "12 - USB Type C, USB microAB": C98 C99 C100 C101 C102 C103 C104 C105 C106 C107 C108 C147 C148 C149 C150 C151 C152 C153 D1 D2 D8 D9 D10 J19 J28 L37 L38 L39 Q4 R147 R148 R149 R150 R151 R152 R153 R214 R234 R235 U17 U18 U19 U31
component class "08 - Ethernet1": C41 C42 C43 C44 C45 C47 C48 C49 C50 C51 C52 C53 C54 C55 C56 C57 C58 C59 C62 J12 L2 L3 L4 Q2 Q11 R16 R69 R70 R71 R72 R73 R74 R75 R81 R82 R83 R84 R85 R86 R87 R88 R89 R90 R91 R92 R93 R94 R95 R96 R97 R98 R99 R100 R101 R102 R160 R244 U9 U11 U23 U29 X1
component class "11 - USB HUB": C81 C82 C83 C84 C85 C86 C87 C88 C89 C90 C91 C92 C93 C94 C95 C96 C97 J18 L9 L10 L11 L12 L13 L14 L15 L29 L30 Q3 Q12 R12 R76 R77 R78 R79 R135 R136 R137 R138 R139 R140 R141 R142 R143 R144 R145 R146 R161 R191 R192 R228 R229 R238 R239 R242 R243 U13 U14 U15 U16 U24 X3
component class "10 - Displays and cameras": C78 C80 J14 J15 J16 J17 L8 L24 L25 L26 L27 L28 L31 L32 L33 L34 L35 L36 R134 R215 R251 R252 R253 R254 U22
component class "13 - Audio": C34 C35 C36 C79 C109 C110 C111 C112 C113 C114 C115 C116 C117 C118 C119 C120 C121 C122 C123 C124 C125 C126 C127 C128 C129 C130 C131 C133 C134 J21 L16 L17 L18 L19 L20 L21 NT1 Q5 Q6 Q9 Q10 R154 R155 R156 R157 R158 R159 R164 R165 R166 R167 R168 R169 R170 R193 R194 R199 U20 U21 U25
component class "14 - I2C, XBee": C37 C38 J22 J23 L22 L23 R171 R172 R173 R174 R175 R176 R177 R178 R185 R186 R187 R188 R189 R190 R196 R197 R198 R240 R241
component class "15 - Expansion connectors, User LEDs, RF signals": D11 D12 J20 J27 Q13 Q14 R108 R109 R203 R204
net class DIFF90: EXPANSION_USB1_D_N EXPANSION_USB1_D_P EXPANSION_USB2_D_N EXPANSION_USB2_D_P NetL9_1 NetL9_4 NetL10_1 NetL10_4 NetL11_1 NetL11_4 NetL12_1 NetL12_4 OTGD_N OTGD_P PCIe/EXPANSION_USB1_D_N PCIe/EXPANSION_USB1_D_P SS3_1_RX_N SS3_1_RX_P SS3_1_TX_N SS3_1_TX_P SS3_2_RX_N SS3_2_RX_P SS3_2_TX_N SS3_2_TX_P SS_1_TX_N SS_1_TX_P SS_2_TX_N SS_2_TX_P USB_OTG1_N USB_OTG1_P USB_OTG2_N USB_OTG2_P USB_PCIe_D_N USB_PCIe_D_P USB_SS3_RX_N USB_SS3_RX_P USB_SS3_TX_N USB_SS3_TX_P USBH1_D_N USBH1_D_P USBH2_D_N USBH2_D_P XBEE/EXPANSION_USB2_D_N XBEE/EXPANSION_USB2_D_P XBEE_D_N XBEE_D_P
component class "03 - CCIMX8X Digital interfaces": R179 R180 R181 R182 R183 R184 R232 TP15 TP16
component class "04 - CCIMX8X RF, PCIe": C137 C138 R10 R222 R223 R224 R225 R226 R227 TP18 TP19 TP20 TP21
component class "07 - Console, UART, CAN": C29 C30 C31 C32 C33 C39 C40 C145 C146 D6 D7 J11 R11 R59 R60 R61 R62 R63 R65 R66 R67 R68 R163 R233 R245 R246 R247 R248 R249 R250 U4 U5 U6 U7 U8 U10
component class "09 - Ethernet2": C60 C61 C63 C65 C66 C67 C68 C69 C70 C71 C72 C73 C74 C75 C76 C77 J13 L5 L6 L7 R80 R103 R104 R105 R106 R107 R113 R114 R115 R116 R118 R119 R120 R121 R122 R123 R124 R125 R126 R127 R128 R129 R130 R131 R132 R133 U12 X2
net class DIFF85: NetR222_2 NetR223_2 NetR224_2 NetR225_2 NetR226_2 NetR227_2 PCIE_CLK_N PCIE_CLK_P PCIE_RX_N PCIE_RX_P PCIE_SOM_CLK_N PCIE_SOM_CLK_P PCIE_TX_N PCIE_TX_P PCIECLK_N PCIECLK_P PCIETX_N PCIETX_P
net class DIFF100: ETH1_TXRXA_N ETH1_TXRXA_P ETH1_TXRXB_N ETH1_TXRXB_P ETH1_TXRXC_N ETH1_TXRXC_P ETH1_TXRXD_N ETH1_TXRXD_P ETH2_TXRXA_N ETH2_TXRXA_P ETH2_TXRXB_N ETH2_TXRXB_P ETH2_TXRXC_N ETH2_TXRXC_P ETH2_TXRXD_N ETH2_TXRXD_P MIPI_CSI0_CLK_N MIPI_CSI0_CLK_P MIPI_CSI0_DATA0_N MIPI_CSI0_DATA0_P MIPI_CSI0_DATA1_N MIPI_CSI0_DATA1_P MIPI_DSI0_CLK_N MIPI_DSI0_CLK_P MIPI_DSI0_DATA0_N MIPI_DSI0_DATA0_P MIPI_DSI0_DATA1_N MIPI_DSI0_DATA1_P MIPI_DSI0_DATA2_N MIPI_DSI0_DATA2_P MIPI_DSI0_DATA3_N MIPI_DSI0_DATA3_P MIPI_DSI1_CLK_N MIPI_DSI1_CLK_P MIPI_DSI1_DATA0_N MIPI_DSI1_DATA0_P MIPI_DSI1_DATA1_N MIPI_DSI1_DATA1_P MIPI_DSI1_DATA2_N MIPI_DSI1_DATA2_P MIPI_DSI1_DATA3_N MIPI_DSI1_DATA3_P NetJ14_2 NetJ14_3 NetJ14_5 NetJ14_6 NetJ14_8 NetJ14_9 NetJ14_11 NetJ14_12 NetJ14_14 NetJ14_15 NetJ16_2 NetJ16_3 NetJ16_5 NetJ16_6 NetJ16_8 NetJ16_9 NetJ16_11 NetJ16_12 NetJ16_14 NetJ16_15
differential pair SS_2_TX: +SS_2_TX_P -SS_2_TX_N
differential pair SS_1_TX: +SS_1_TX_P -SS_1_TX_N
differential pair XBEE/EXPANSION_USB2_D: +XBEE/EXPANSION_USB2_D_P -XBEE/EXPANSION_USB2_D_N
differential pair PCIe/EXPANSION_USB1_D: +PCIe/EXPANSION_USB1_D_P -PCIe/EXPANSION_USB1_D_N
differential pair EXPANSION_USB2_D: +EXPANSION_USB2_D_P -EXPANSION_USB2_D_N
differential pair EXPANSION_USB1_D: +EXPANSION_USB1_D_P -EXPANSION_USB1_D_N
differential pair XBEE_D: +XBEE_D_P -XBEE_D_N
differential pair USB_PCIe_D: +USB_PCIe_D_P -USB_PCIe_D_N
differential pair SPKR: +SPKR_P -SPKR_N
differential pair SPKL: +SPKL_P -SPKL_N
differential pair USBH1_D: +USBH1_D_P -USBH1_D_N
differential pair USBH2_D: +USBH2_D_P -USBH2_D_N
differential pair ETH1_TXRXA: +ETH1_TXRXA_P -ETH1_TXRXA_N
differential pair ETH1_TXRXB: +ETH1_TXRXB_P -ETH1_TXRXB_N
differential pair ETH1_TXRXC: +ETH1_TXRXC_P -ETH1_TXRXC_N
differential pair ETH1_TXRXD: +ETH1_TXRXD_P -ETH1_TXRXD_N
differential pair ETH2_TXRXA: +ETH2_TXRXA_P -ETH2_TXRXA_N
differential pair ETH2_TXRXB: +ETH2_TXRXB_P -ETH2_TXRXB_N
differential pair ETH2_TXRXC: +ETH2_TXRXC_P -ETH2_TXRXC_N
differential pair ETH2_TXRXD: +ETH2_TXRXD_P -ETH2_TXRXD_N
differential pair MIPI_CSI0_CLK: +MIPI_CSI0_CLK_P -MIPI_CSI0_CLK_N
differential pair MIPI_CSI0_DATA0: +MIPI_CSI0_DATA0_P -MIPI_CSI0_DATA0_N
differential pair MIPI_CSI0_DATA1: +MIPI_CSI0_DATA1_P -MIPI_CSI0_DATA1_N
differential pair MIPI_DSI0_CLK: +MIPI_DSI0_CLK_P -MIPI_DSI0_CLK_N
differential pair MIPI_DSI0_DATA0: +MIPI_DSI0_DATA0_P -MIPI_DSI0_DATA0_N
differential pair MIPI_DSI0_DATA1: +MIPI_DSI0_DATA1_P -MIPI_DSI0_DATA1_N
differential pair MIPI_DSI0_DATA2: +MIPI_DSI0_DATA2_P -MIPI_DSI0_DATA2_N
differential pair MIPI_DSI0_DATA3: +MIPI_DSI0_DATA3_P -MIPI_DSI0_DATA3_N
differential pair MIPI_DSI1_CLK: +MIPI_DSI1_CLK_P -MIPI_DSI1_CLK_N
differential pair MIPI_DSI1_DATA0: +MIPI_DSI1_DATA0_P -MIPI_DSI1_DATA0_N
differential pair MIPI_DSI1_DATA1: +MIPI_DSI1_DATA1_P -MIPI_DSI1_DATA1_N
differential pair MIPI_DSI1_DATA2: +MIPI_DSI1_DATA2_P -MIPI_DSI1_DATA2_N
differential pair MIPI_DSI1_DATA3: +MIPI_DSI1_DATA3_P -MIPI_DSI1_DATA3_N
differential pair PCIE_CLK: +PCIE_CLK_P -PCIE_CLK_N
differential pair PCIE_RX: +PCIE_RX_P -PCIE_RX_N
differential pair PCIE_TX: +PCIE_TX_P -PCIE_TX_N
differential pair PCIECLK: +PCIECLK_P -PCIECLK_N
differential pair PCIETX: +PCIETX_P -PCIETX_N
differential pair SS3_1_RX: +SS3_1_RX_P -SS3_1_RX_N
differential pair SS3_2_RX: +SS3_2_RX_P -SS3_2_RX_N
differential pair USB_SS3_RX: +USB_SS3_RX_P -USB_SS3_RX_N
differential pair USB_SS3_TX: +USB_SS3_TX_P -USB_SS3_TX_N
differential pair OTGD: +OTGD_P -OTGD_N
differential pair PCIE_SOM_CLK: +PCIE_SOM_CLK_P -PCIE_SOM_CLK_N
differential pair MIC: +MIC_P -MIC_N
differential pair USB_OTG2: +USB_OTG2_P -USB_OTG2_N
differential pair " ": +USB_OTG1_P -USB_OTG1_N

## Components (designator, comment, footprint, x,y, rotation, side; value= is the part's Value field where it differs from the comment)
C1 "100uF" CAPMP3216X120N 56.5,53.4 r270 bottom
C2 "10uF" CAPC1005X55N#1 53.325,53.775 r90 bottom
C3 "1.0uF" CAPC1005X55N#1 54.375,53.775 r90 bottom
C4 "1.0uF" CAPC1005X55L 40.75,37.92 r90 bottom
C5 "2.2UF" CAPC1608X90N 42.2,31.75 r180 bottom
C6 "10uF" CAPC1005X55N#1 38.45,60.9 r270 bottom
C7 "100uF" CAPMP3216X120N 37.525,63.875 r0 bottom
C8 "22µF" CAPC1608X90N 37.625,67.675 r180 bottom
C9 "100nF" CAPC1005X55N#1 37.6,66.15 r180 bottom
C10 "47uF" CAPC2013X145N 56.15,63.3 r270 bottom
C11 "22µF" CAPC1608X90N 54.55,63.3 r270 bottom
C12 "100nF" CAPC1005X55N#1 53.3,63.3 r270 bottom
C13 "100nF" CAPC1005X55N#1 47.2,63.4 r180 bottom
C14 "47pF" CAPC1005X55N#1 47.2,62.2 r180 bottom
C15 "10uF" CAPC2013X135N 60.2,68.3 r90 bottom
C16 "10uF" CAPC2013X135N 58.3,68.3 r90 bottom
C17 "10uF" CAPC2013X135N 56.4,68.3 r90 bottom
C18 "10uF" CAPC2013X135N 54.5,68.3 r90 bottom
C19 "100uF" CAPMP3216X120N 80.4,58.4 r0 bottom
C20 "100uF" CAPMP3216X120N 84.6,63.8 r180 top
C21 "100uF" CAPMP3216X120N 89.975,63.825 r180 top
C22 "100nF" CAPC1005X55N#1 78.75,63.75 r270 top
C23 "100nF" CAPC1005X55N#1 84.025,71.125 r0 bottom
C24 "100nF" CAPC1005X55N#1 89.6,59.6 r0 bottom
C25 "100nF" CAPC1005X55N#1 67.1,59.675 r180 bottom
C26 "100nF" CAPC1005X55N#1 86.25,71.125 r180 bottom
C27 "10uF" CAPC1005X55N#1 97.8,33.875 r180 top
C28 "100nF" CAPC1005X55N#1 97.8,34.8 r180 top
C29 "100nF" CAPC1005X55N#1 26.15,43.975 r270 bottom
C30 "100nF" CAPC1005X55N#1 26.175,48.85 r90 bottom
C31 "100nF" CAPC1005X55N#1 25.55,29.675 r0 top
C32 "100nF" CAPC1005X55N#1 21.65,43.9 r180 top
C33 "100nF" CAPC1005X55N#1 14.959,53.281 r180 bottom
C34 "1.0uF" CAPC1005X55L 30.8,53.1 r180 bottom
C35 "1.0uF" CAPC1005X55L 30.8,52.1 r180 bottom
C36 "1.0uF" CAPC1005X55L 32.9,50.3 r180 bottom
C37 "100uF" CAPC3216X190N 11.8,52.1 r90 top
C38 "100nF" CAPC1005X55N#1 13.725,51.075 r90 top
C39 "100nF" CAPC1005X55N#1 14.175,35 r270 bottom
C40 "100nF" CAPC1005X55N#1 15.5,35 r270 bottom
C41 "1nF" CAPC1005X55N#1 34.9,22.05 r0 bottom
C42 "22pF" CAPC1005X55N#1 31.975,29.275 r90 bottom
C43 "22pF" CAPC1005X55N#1 31.975,31.125 r270 bottom
C44 "100nF" CAPC1005X55N#1 28.55,42.2 r180 bottom
C45 "100nF" CAPC1005X55N#1 14.6,19.107 r0 bottom
C46 "100nF" CAPC1005X55N#1 96.215,44.1 r180 top
C47 "10uF" CAPC1005X55N#1 31.725,33.425 r270 bottom
C48 "100nF" CAPC1005X55N#1 30.7,33.425 r270 bottom
C49 "100nF" CAPC1005X55N#1 26.14,24.167 r0 bottom
C50 "1.0uF" CAPC1005X55N#1 26.14,25.192 r0 bottom
C51 "100nF" CAPC1005X55N#1 19.9,30.3 r270 bottom
C52 "1.0uF" CAPC1005X55N#1 20.85,29.875 r270 bottom
C53 "1.0uF" CAPC1005X55N#1 31.25,25.6 r180 bottom
C54 "10uF" CAPC1005X55N#1 27.3,38.275 r0 bottom
C55 "100nF" CAPC1005X55N#1 27.2,37.35 r0 bottom
C56 "100nF" CAPC1005X55N#1 31.25,27.625 r180 bottom
C57 "100nF" CAPC1005X55N#1 24.625,24.675 r90 bottom
C58 "0.22uF" CAPC1005X55N#1 28.625,25.925 r90 bottom
C59 "0.22uF" CAPC1005X55N#1 26.125,34.6 r0 bottom
C60 "22pF" CAPC1005X55N#1 30.2,36.1 r180 top
C61 "22pF" CAPC1005X55N#1 27.9,36.1 r0 top
C62 "100nF" CAPC1005X55N#1 27.3,39.425 r0 bottom
C63 "100nF" CAPC1005X55N#1 31.2,19.2 r0 top
C64 "100nF" CAPC1005X55N#1 98.215,44.1 r0 top
C65 "10uF" CAPC1005X55N#1 26.4,37 r90 top
C66 "100nF" CAPC1005X55N#1 25.45,37 r90 top
C67 "100nF" CAPC1005X55N#1 34.925,42.5 r270 top
C68 "1.0uF" CAPC1005X55N#1 34,42.5 r270 top
C69 "100nF" CAPC1005X55N#1 29.375,48.1 r270 bottom
C70 "1.0uF" CAPC1005X55N#1 29.375,48.1 r270 top
C71 "1.0uF" CAPC1005X55N#1 32.2,38.425 r180 top
C72 "10uF" CAPC1005X55N#1 22.5,41.4 r270 top
C73 "100nF" CAPC1005X55N#1 21.525,41.4 r270 top
C74 "100nF" CAPC1005X55N#1 32.2,37.275 r180 top
C75 "100nF" CAPC1005X55N#1 34.1,43.875 r180 top
C76 "0.22uF" CAPC1005X55N#1 33.625,39.5 r90 top
C77 "0.22uF" CAPC1005X55N#1 24.95,41.875 r270 top
C78 "100nF" CAPC1005X55N#1 74.95,63.8 r90 top
C79 "1.0uF" CAPC1005X55L 33.075,49.325 r180 bottom
C80 "100nF" CAPC1005X55N#1 20.125,64.875 r180 bottom
C81 "33pF" CAPC1005X55N#1 23.919,57.191 r90 top
C82 "33pF" CAPC1005X55N#1 23.925,55.3 r270 top
C83 "1.0uF" CAPC1005X55N#1 27.05,59.05 r90 bottom
C84 "1.0uF" CAPC1005X55N#1 55.375,19.925 r0 bottom
C85 "10uF" CAPC1005X55N#1 47.95,18.7 r270 bottom
C86 "100nF" CAPC1005X55N#1 49.025,18.7 r270 bottom
C87 "10uF" CAPC1005X55N#1 47.95,18.7 r270 top
C88 "100nF" CAPC1005X55N#1 49.025,18.7 r270 top
C89 "1nF" CAPC1005X55N#1 39.225,60.65 r270 top
C90 "10uF" CAPC1005X55N#1 24.6,53.125 r90 top
C91 "100nF" CAPC1005X55N#1 24.6,52.325 r0 bottom
C92 "100nF" CAPC1005X55N#1 33.6,54.225 r180 top
C93 "100nF" CAPC1005X55N#1 33.6,57.25 r180 top
C94 "100nF" CAPC1005X55N#1 23.919,59.091 r270 top
C95 "100nF" CAPC1005X55N#1 29.425,61 r180 bottom
C96 "100nF" CAPC1005X55N#1 33.6,56.275 r180 top
C97 "100nF" CAPC1005X55N#1 19.8,53.5 r0 top
C98 "100nF" CAPC1005X55N#1 70.475,11.075 r90 bottom
C99 "100nF" CAPC1005X55N#1 70.4,16.3 r0 top
C100 "100nF" CAPC1005X55N#1 76.15,15.525 r180 top
C101 "2.2µF" CAPC1005X55L 76.15,16.65 r180 top
C102 "2.2µF" CAPC1005X55L 77.26,18.14 r90 top
C103 "10uF" CAPC1005X55N#1 71.7,11.075 r270 bottom
C104 "10uF" CAPC1005X55N#1 71.13,20.55 r270 bottom
C105 "100nF" CAPC1005X55N#1 72.08,20.55 r270 bottom
C106 "10uF" CAPC1005X55N#1 72.05,16.175 r90 bottom
C107 "100nF" CAPC1005X55N#1 71.025,16.175 r90 bottom
C108 "100nF" CAPC1005X55N#1 69.95,16.175 r90 bottom
C109 "1.0uF" CAPC1005X55L 36.425,55.675 r0 bottom
C110 "1.0uF" CAPC1005X55L 34.25,53 r90 bottom
C111 "1.0uF" CAPC1005X55L 35.15,53 r90 bottom
C112 "10pF" CAPC1005X55N#1 30.8,54 r180 bottom
C113 "10pF" CAPC1005X55N#1 30.8,51.2 r180 bottom
C114 "10pF" CAPC1005X55N#1 32.9,51.2 r0 bottom
C115 "10pF" CAPC1005X55N#1 33.05,48.075 r180 bottom
C116 "10pF" CAPC1005X55N#1 30.8,48 r180 bottom
C117 "10pF" CAPC1005X55N#1 31.2,44.8 r0 bottom
C118 "100nF" CAPC1005X55N#1 44.3,48.1 r0 bottom
C119 "100nF" CAPC1005X55N#1 42.2,52.45 r90 bottom
C120 "10uF" CAPC1005X55N#1 38.5,55.75 r0 bottom
C121 "1.0uF" CAPC1005X55N#1 40,55.1 r90 bottom
C122 "1.0uF" CAPC1005X55N#1 38.5,54.75 r180 bottom
C123 "1.0uF" CAPC1005X55N#1 35.625,41.875 r180 bottom
C124 "10uF" CAPC1005X55N#1 41.125,41.7 r180 bottom
C125 "1.0uF" CAPC1005X55N#1 39.3,41.7 r180 bottom
C126 "1.0uF" CAPC1005X55N#1 39.3,42.625 r180 bottom
C127 "1.0uF" CAPC1005X55N#1 35.625,42.925 r0 bottom
C128 "1.0uF" CAPC1005X55N#1 33.192,46.15 r0 bottom
C129 "1.0uF" CAPC1005X55N#1 33.192,45.225 r0 bottom
C130 "2.2µF" CAPC1005X55N#1 37,52.975 r90 bottom
C131 "1.0uF" CAPC1005X55N#1 38,52.95 r270 bottom
C132 "1.0uF" CAPC1005X55N#1 85.725,20.95 r90 bottom
C133 "1nF" CAPC1005X55N#1 41.175,60.1 r180 bottom
C134 "1nF" CAPC1005X55N#1 36.4,36.3 r0 bottom
C135 "1uF" CAPC1608X90N 47.6,65.3 r270 bottom
C136 "15nF" CAPC1005X55N#1 49.35,59.5 r90 bottom
C137 "220nF" CAPC0603X33N 82.7,49.8 r270 bottom
C138 "220nF" CAPC0603X33N 81.55,49.8 r270 bottom
C139 "100nF" CAPC1005X55N#1 70.275,68.525 r90 top
C140 "100nF" CAPC1005X55N#1 71.3,68.525 r90 top
C142 "15nF" CAPC1005X55N#1 79.7,19.9 r180 bottom
C143 "2.2UF" CAPC1608X90N 42.9,39.6 r90 bottom
C145 "100nF" CAPC1005X55N#1 25.55,34.55 r180 top
C146 "100nF" CAPC1005X55N#1 18.8,40.325 r270 bottom
C147 "1.0uF" CAPC1005X55N#1 46,36 r90 bottom
C148 "100nF" CAPC1005X55N#1 44.8,32.6 r90 top
C149 "10uF" CAPC1005X55N#1 42.9,32.6 r90 top
C150 "100nF" CAPC1005X55N#1 66.825,13.15 r270 bottom
C151 "100nF" CAPC1005X55N#1 67.85,13.15 r270 bottom
C152 "100nF" CAPC1005X55N#1 74.3,12.8 r270 top
C153 "100nF" CAPC1005X55N#1 73.275,12.8 r270 top
C154 "10uF" CAPC1005X55N#2 28,62.95 r180 bottom
C155 "100uF" CAPMP3216X120N 31.135,64 r270 bottom
C156 "22µF" CAPC1608X90N 28.025,65.7 r0 bottom
C157 "100nF" CAPC1005X55N#2 27.975,67.225 r0 bottom
C158 "10uF" CAPC1005X55N#2 23.425,62.95 r180 bottom
C159 "100uF" CAPMP3216X120N 25.7,63.475 r270 bottom
C160 "22µF" CAPC1608X90N 23.4,65.7 r0 bottom
C161 "100nF" CAPC1005X55N#2 23.325,67.35 r0 bottom
C162 "4.7uF" CAPC1005X55N#2 44.55,47.9 r270 top
CAD1 "TC2050-IDC-NL" TC_TC2050-IDC-NL#1 38.635,23.87 r270 bottom
CAD2 "TC2050-IDC-NL" TC_TC2050-IDC-NL#2 14.765,59.43 r270 bottom locked
D1 "IP4292CZ10" SON50P250X100X50-10N 70.9,10.85 r90 top
D2 "ESD9B5.0ST5G" SODFL1006X43N12 58.325,6.6 r270 bottom
D3 "MMSZ5231BT1G" SOD3716X135N 85.65,16.475 r90 bottom
D4 "BAT54CWT1G" SOT65P210X100-3AN 39.569,36.159 r180 bottom
D5 "597-3301-507F" LEDM3020X130N 33.3,28.9 r90 top
D6 "ESD9B3.3ST5G" SODFL1006X43AN12 96,53.875 r0 top
D7 "ESD9B3.3ST5G" SODFL1006X43AN12 97.925,53.9 r180 top
D8 "1N5819HW-7-F" SOD3716X135N 73.38,17.85 r90 bottom
D9 "IP4292CZ10" SON50P250X100X50-10N 68.1,10.8 r270 top
D10 "IP4292CZ10" SON50P250X100X50-10N 73.95,10.875 r90 top
D11 "597-3301-507F" LEDM3020X130N 30.25,28.9 r90 top
D12 "597-3401-507F" LEDM3020X130N 27.75,28.9 r90 top
D13 "DB2J31400L" SODFL2513X80N 44.325,50.9 r270 top
D14 "SMA6J5.0A" DIOM5127X229AN 76.75,19.805 r90 bottom
FIDUCIAL1 "40mil FID" fiducial_40mil_round 98.5,8.9 r90 bottom
FIDUCIAL2 "40mil FID" fiducial_40mil_round 28.675,70.1 r90 bottom
FIDUCIAL3 "40mil FID" fiducial_40mil_round 94.4,65.4 r90 bottom
FIDUCIAL4 "40mil FID" fiducial_40mil_round 1.175,65.475 r90 top
FIDUCIAL5 "40mil FID" fiducial_40mil_round 6.2,5.4 r90 top
FIDUCIAL6 "40mil FID" fiducial_40mil_round 312.5,2.5 r90 top
FIDUCIAL7 "40mil FID" fiducial_40mil_round 49.15,62.675 r270 top
FIDUCIAL8 "40mil FID" fiducial_40mil_round 98.5,8.9 r90 top
FIDUCIAL9 "40mil FID" fiducial_40mil_round 94.4,65.4 r90 top
FIDUCIAL10 "40mil FID" fiducial_40mil_round 1.175,65.475 r90 bottom
FIDUCIAL11 "40mil FID" fiducial_40mil_round 18.8,19.45 r90 bottom
FIDUCIAL12 "40mil FID" fiducial_40mil_round 312.5,2.5 r90 bottom
FIL1 "NFM21PC475B1A3D" FIL_NFM21P 83.95,16.6 r180 top
H1 "125mil" MH_185_125_NP -7.5,-4 r0 top locked
H2 "125mil" MH_185_125_NP -7.5,72 r0 top locked
H3 "125mil" MH_185_125_NP 312.5,72 r0 top
H4 "125mil" MH_185_125_NP 312.5,-4 r0 top
J2 "1x2P" MOLEX_53047-0210 2.2,7.85 r90 top
J3 "1x2P" MOLEX_53047-0210 5.7,7.85 r90 top
J4 "CSCD443CCS011B00G" conn_CSCD443CCS011B00G 90,11.904 r90 top locked
J5 "640456-2" TE_640456-2 97.225,14.225 r0 top
J6 "1x2P" MOLEX_53047-0210 9.2,7.85 r90 top
J7 "PCIe Minicard" FOXCONN_AS0B221-S68Q-7H 65.6,65.4 r0 bottom locked
J8 "78727-0001" MOLEX_78727-0001 98.67,45.38 r0 bottom locked
J9 "FTSH-105-01-F-DV" SAMTEC_FTSH-105-01-F-DV 14.8,59.4 r0 top
J10 "500873-0806" MOLEX_500873-0806 94.75,28.4 r90 bottom
J11 "1x4" MOLEX_53047-0410 98.15,57.475 r180 top
J12 "RJ45" XMULTIPLE_XMG-J1B211 14.501,16.005 r0 top locked
J13 "RJ45" XMULTIPLE_XMG-J1B211 32.751,16.005 r0 top locked
J14 "DF14A-20P-1.25H(25)" HIROSE_DF14A-20P-1.25H 21.375,67.65 r0 top locked
J15 "SFW15S-2STE1LF" FCI_SFW15S-2STE1LF 82.45,67.925 r0 top locked
J16 "DF14A-20P-1.25H(25)" HIROSE_DF14A-20P-1.25H 52.175,67.65 r0 top
J17 "1x20P" omron_xf2m-2015-1a 14,68.6 r0 bottom locked
J18 "KUSBX-AS2N" KYCON_KUSBX-AS2N_Flex 52.301,13.485 r0 top locked
J19 "USB_C" MOLEX_201267-0005 70.1,3.975 r0 top
J20 "802-10-040-001000" "MILLMAX_ 802-10-040-62-001000" 1.425,60.325 r0 top
J21 "SJ1-3533NG" CUI_SJ1-3533N 80.75,1.225 r90 top
J22 "SMM-110-02-F-S-P-TR" SAMTEC_SMM-110-02-F-S 16.992,43.875 r270 top locked
J23 "SMM-110-02-F-S-P-TR" SAMTEC_SMM-110-02-F-S 38.992,43.875 r270 top locked
J27 "802-10-040-001000" "MILLMAX_ 802-10-040-62-001000" 6.575,60.325 r0 top
J28 "KMMX-ABSMT5SG-30TR" KYCON_KMMX-ABSMT5 56,1.7 r180 bottom
L1 "1.5UH" INDM_SRP4020TA 51.2,67.575 r90 bottom
L2 "120" INDC1005X60N 26.6,22.575 r90 bottom
L3 "4.7uH" INDC2520X100L60N 29.8,36.35 r90 bottom
L4 "120" INDC1005X60N 27.225,36 r0 bottom
L5 "120" INDC1005X60N 34.9,40.5 r90 top
L6 "4.7uH" INDC2520X100L60N 22.95,38.75 r180 top
L7 "120" INDC1005X60N 23.5,41.4 r270 top
L8 "220" INDC2013X110N 24.275,69.7 r180 bottom
L9 "744231121" FIL_DLW21H 54.975,17.55 r270 bottom
L10 "744231121" FIL_DLW21H 56.625,17.55 r270 bottom
L11 "744231121" FIL_DLW21H 31.475,51.225 r180 top
L12 "744231121" FIL_DLW21H 13.925,25.577 r270 bottom
L13 "220" INDC2013X110N 61,18.5 r180 bottom
L14 "220" INDC2013X110N 60.6,18.525 r180 top
L15 "220" INDC2013X110N 33.1,62.2 r270 top
L16 "1.8K" INDC1005X60N 33.7,55.325 r270 bottom
L17 "1.8K" INDC1005X60N 34.9,55.325 r270 bottom
L18 "1.8K" INDC1005X60N 28.825,53.95 r0 bottom
L19 "1.8K" INDC1005X60N 28.825,52.675 r0 bottom
L20 "1.8K" INDC1005X60N 30.825,50.1 r0 bottom
L21 "1.8K" INDC1005X60N 30.8,49.025 r0 bottom
L22 "220" INDC2013X110N 19.875,58.275 r90 bottom
L23 "220" INDC2013X110N 19.875,59.975 r270 bottom
L24 "DLP11SN900" FIL_DLP11S 31.075,62.625 r90 top
L25 "DLP11SN900" FIL_DLP11S 27.325,62.625 r90 top
L26 "DLP11SN900" FIL_DLP11S 23.575,62.625 r90 top
L27 "DLP11SN900" FIL_DLP11S 20.15,62.775 r90 top
L28 "DLP11SN900" FIL_DLP11S 17.8,63.1 r180 top
L29 "220" INDC2013X110N 51.5,18.5 r180 bottom
L30 "220" INDC2013X110N 51.5,18.5 r180 top
L31 "DLP11SN900" FIL_DLP11S 62.2,62.8 r90 top
L32 "DLP11SN900" FIL_DLP11S 58.5,62.8 r90 top
L33 "DLP11SN900" FIL_DLP11S 54.7,62.8 r90 top
L34 "DLP11SN900" FIL_DLP11S 51,62.8 r90 top
L35 "DLP11SN900" FIL_DLP11S 47.2,62.8 r90 top
L36 "220" INDC2013X110N 41,61.4 r90 top
L37 "220" INDC2013X110N 48.025,22.3 r180 bottom
L38 "744231121" FIL_DLW21H 56.975,6.775 r270 bottom
L39 "220" INDC2013X110N 54.5,6.55 r0 bottom
NT1 "NET TIE" NET_TIE_4mil 34.325,47 r180 bottom net-tie
Q1 "2N7002T" SOTFL50P160X80_GSD-3N 82.9,20.2 r270 bottom
Q2 "2N7002T" SOTFL50P160X80_GSD-3N 33,21.2 r90 bottom
Q3 "2N7002T" SOTFL50P160X80_GSD-3N 38.55,62.825 r180 top
Q4 "2N7002T" SOTFL50P160X80_GSD-3N 72,22.6 r270 bottom
Q5 "2N7002T" SOTFL50P160X80_GSD-3N 37.25,31.3 r180 bottom
Q6 "NTR4003NT1G" SOT95P240X110_GSD-3N 42.1,66.1 r0 bottom
Q7 "MMBT3906LT1G" SOT95P240X110-3N 83,16.5 r90 bottom
Q8 "2N7002T" SOTFL50P160X80_GSD-3N 35.75,28.9 r0 top
Q9 "NTR4003NT1G" SOT95P240X110_GSD-3N 36.5,34.1 r90 bottom
Q10 "NTR4003NT1G" SOT95P240X110_GSD-3N 41.8,62.4 r270 bottom
Q11 "NTR4003NT1G" SOT95P240X110_GSD-3N 34.075,25.625 r90 bottom
Q12 "NTR4003NT1G" SOT95P240X110_GSD-3N 35.6,61.5 r180 top
Q13 "2N7002T" SOTFL50P160X80_GSD-3N 33.66,32 r90 top
Q14 "2N7002T" SOTFL50P160X80_GSD-3N 33.3,34.3 r90 top
R1 "0" RESC2013X70N 51.075,53.825 r180 bottom
R2 "0" RESC1005X40N#1 30.075,67.225 r180 bottom
R3 "0" RESC1005X40N#1 25.475,67.35 r180 bottom
R4 "0" RESC1005X40N#1 69.425,58.9 r180 bottom
R5 "0" RESC1005X40N#1 81.1,40.5 r0 bottom
R6 "0" RESC1005X40N#1 81.1,41.6 r0 bottom
R7 "0" RESC1005X40N#1 81.1,39.4 r0 bottom
R8 "0" RESC1005X40N#1 55.45,37.875 r180 bottom
R9 "0" RESC1005X40N#1 56.6,32.4 r180 bottom
R10 "10.0K" RESC1005X40N#1 81.55,22.3 r90 bottom
R11 "0" RESC1005X40N#1 18.1,26.56 r90 top
R12 "10.0K" RESC1005X40N#1 81.625,33.55 r90 bottom
R13 "0" RESC1005X40N#1 14.12,26.3 r0 top
R14 "0" RESC1005X40N#1 42.5,19.7 r180 bottom
R15 "51K" RESC1005X40N#1 16.02,26.3 r0 top
R16 "10.0K" RESC1005X40N#1 20.5,39.55 r270 bottom
R17 "100K" RESC1005X40N#1 21.75,21.5 r180 bottom
R18 "0" RESC1005X40N#1 8.5,4.8 r0 top
R19 "270" RESC2013X70N 81.8,13.6 r180 bottom
R20 "10.0K" RESC1005X40N#1 84,13.7 r90 bottom
R21 "10.0K" RESC1005X40N#1 81.4,18.5 r270 bottom
R22 "0.0" RESC2013X70N 79.05,15.55 r180 bottom
R23 "1.0K" RESC1005X40N#1 80.6,20.9 r0 bottom
R24 "470K" RESC1005X40N#1 85.175,19.45 r180 bottom
R25 "2.2M" RESC1005X40N#1 84.65,20.95 r90 bottom
R26 "12K" RESC1609X55N 42.2,33.25 r180 bottom
R27 "20K" RESC1609X55N 44.75,32.55 r90 bottom
R28 "0" RESC1005X40N#1 38.9,33.4 r270 bottom
R29 "0" RESC1005X40N#1 42.5,21.1 r180 bottom
R30 "49.9" RESC1005X40N#1 92.825,45.2 r180 top
R31 "0.0" RESC2013X70N 40.35,39.92 r0 bottom
R32 "4.7K" RESC1005X40N#1 41.7,20.3 r270 top
R33 "100K" RESC1005X40N#1 38.5,25.7 r180 top
R34 "0" RESC1005X40N#1 31.2,20.2 r180 top
R35 "4.7K" RESC1005X40N#1 29.7,22.3 r270 top
R36 "4.7K" RESC1005X40N#1 43.22,29.275 r0 top
R37 "100K" RESC1005X40N#1 44.18,29.275 r180 top
R38 "4.7K" RESC1005X40N#1 43.22,30.4 r0 top
R39 "100K" RESC1005X40N#1 44.18,30.4 r180 top
R40 "100K" RESC1005X40N#1 34.35,61.2 r270 bottom
R41 "0" RESC1609X55N 34.975,65.95 r180 bottom
R42 "220" RESC1005X40N#1 33.3,26.3 r180 top
R43 "470K" RESC1005X40N#1 52.3,62.65 r90 bottom
R44 "470K" RESC1005X40N#1 52.3,60.7 r90 bottom
R45 "0" RESC1005X40N#1 44.4,63.975 r270 bottom
R46 "100K" RESC1005X40N#1 50.4,59.5 r90 bottom
R47 "100K" RESC1005X40N#1 44.4,62.1 r270 bottom
R48 "2R" RESC1609X55N 45.6,64.3 r90 bottom
R49 "53.6k" RESC1609X55N 46.1,60.2 r270 bottom
R50 "12K" RESC1609X55N 47.6,60.2 r90 bottom
R51 "10.0K" RESC1005X40N#1 56.675,34.8 r0 bottom
R52 "10.0K" RESC1005X40N#1 68.4,67.2 r270 top
R53 "22.1K" RESC1005X40N#1 94.7,34.4 r90 top
R54 "100K" RESC1005X40N#1 82.75,28.45 r90 bottom
R55 "10.0K" RESC1005X40N#1 94.7,36.25 r270 top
